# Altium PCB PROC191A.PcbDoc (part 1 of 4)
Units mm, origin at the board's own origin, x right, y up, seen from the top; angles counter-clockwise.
Board outline 150 x 100 mm, 6 copper layers (L1, L2, L3, L4, L5, L6), stack 1.608 mm thick; 309 components, 191 nets, 851 pads, 778 vias.
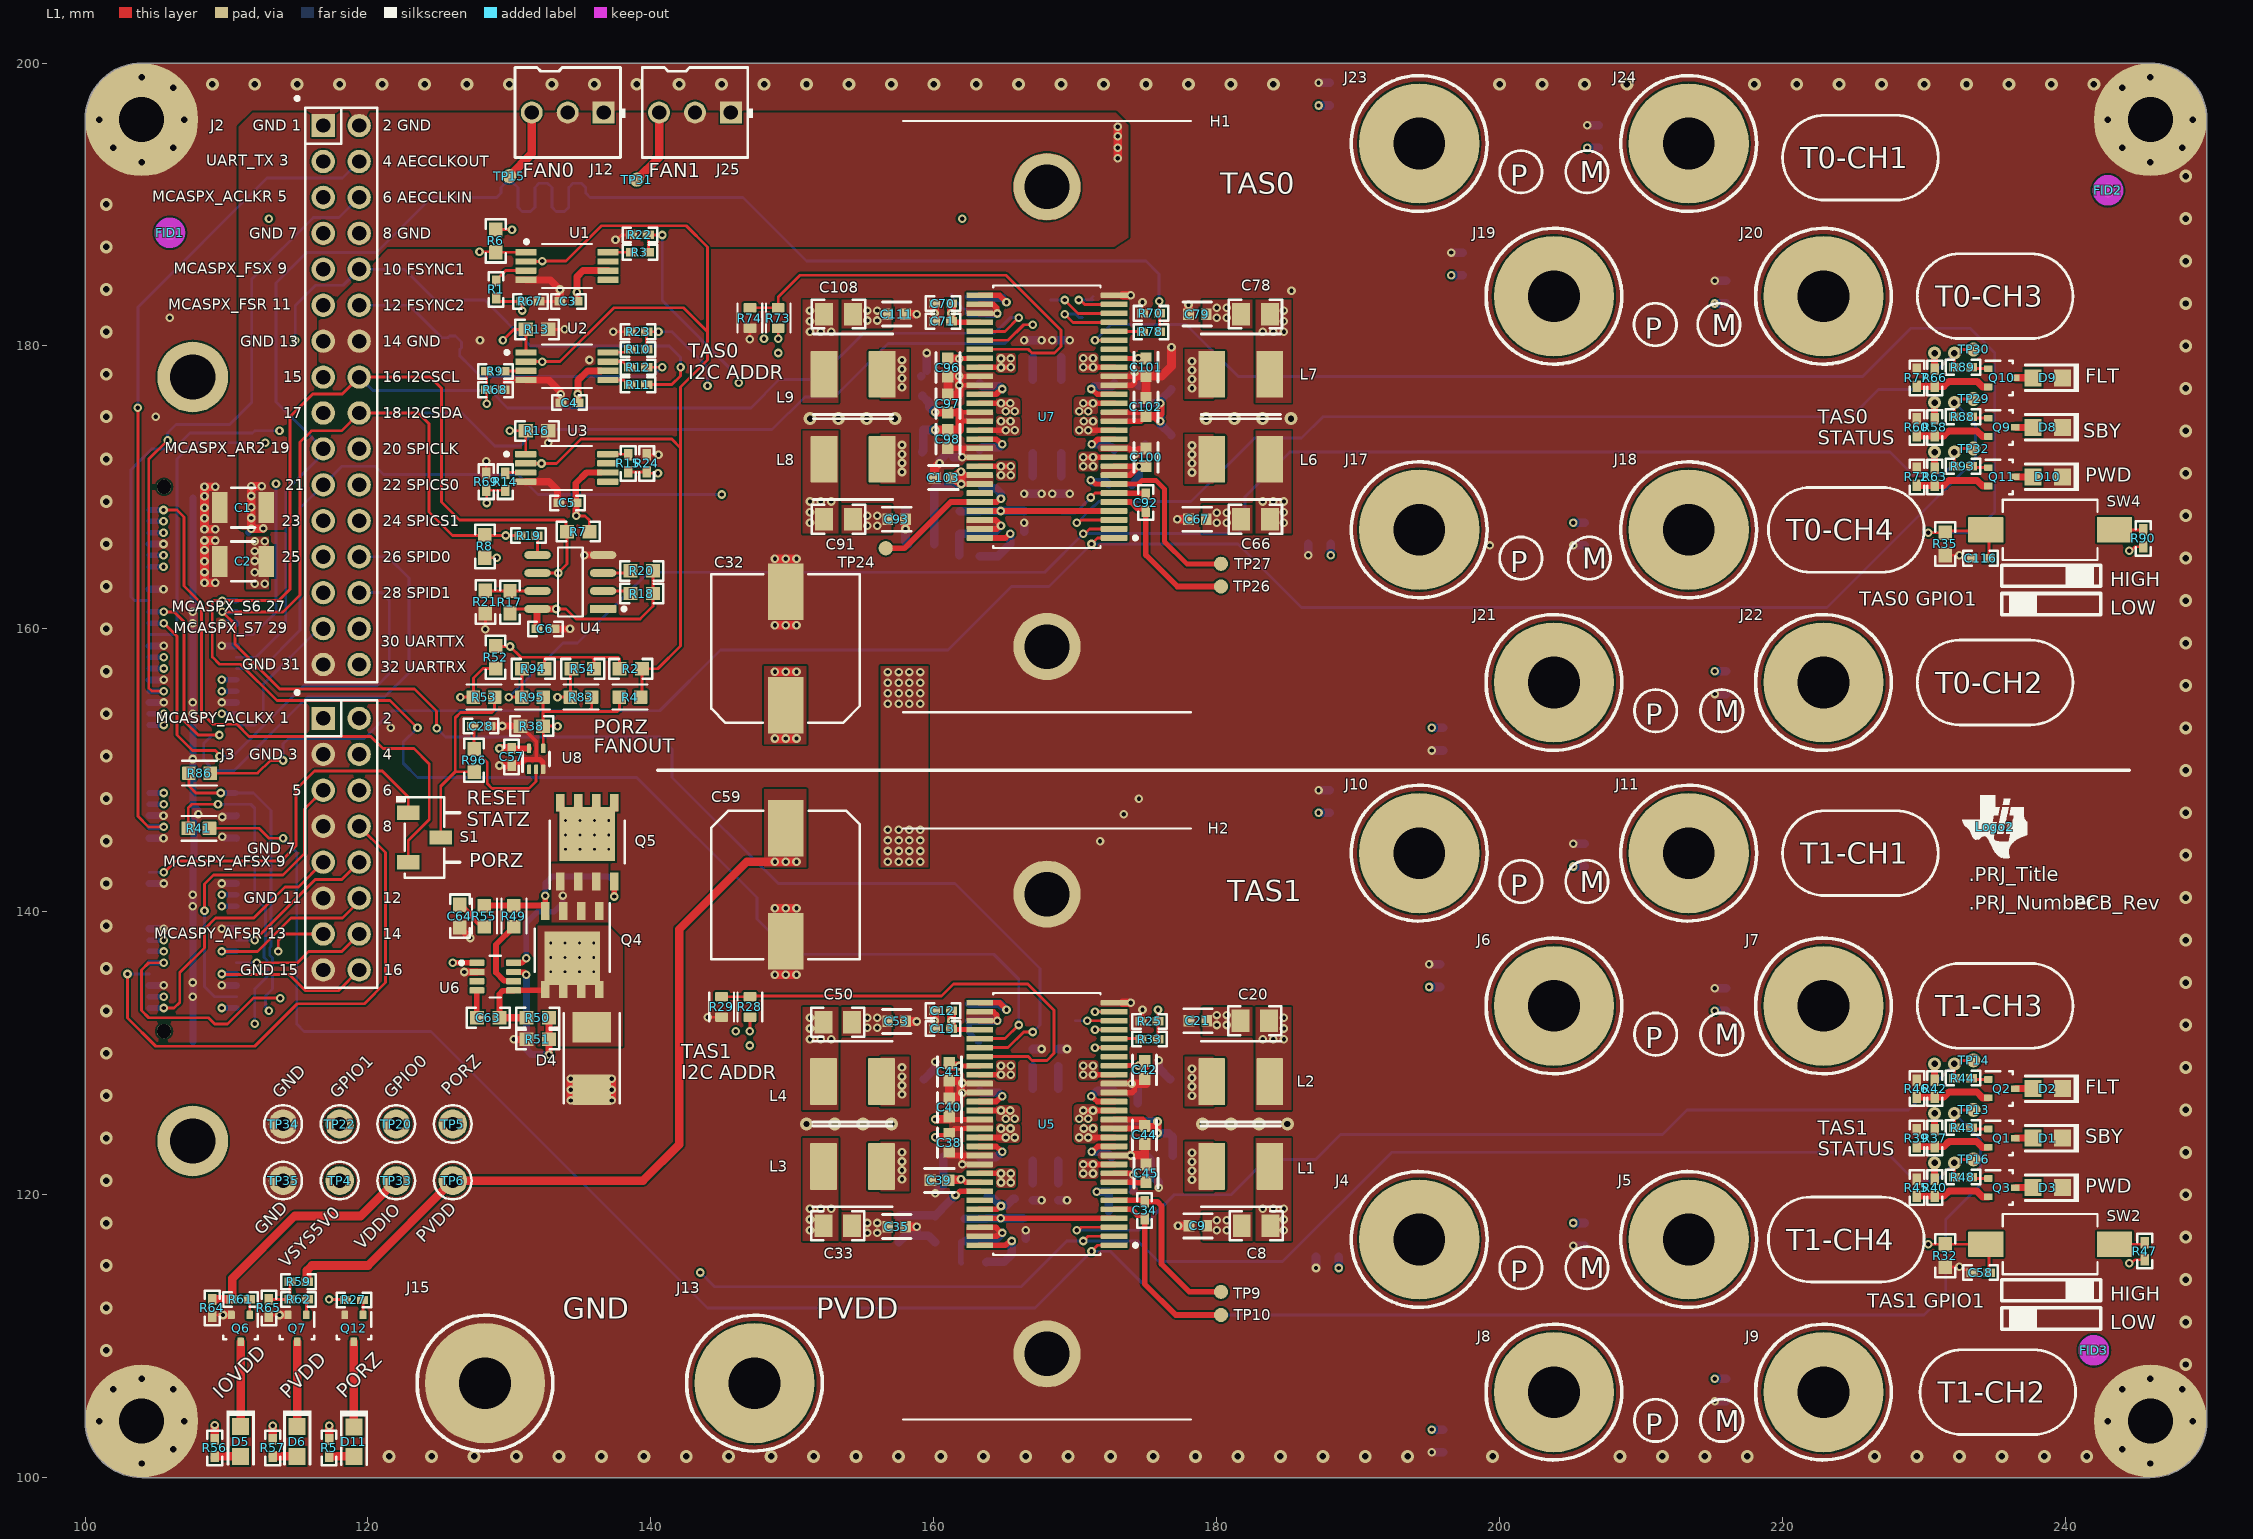
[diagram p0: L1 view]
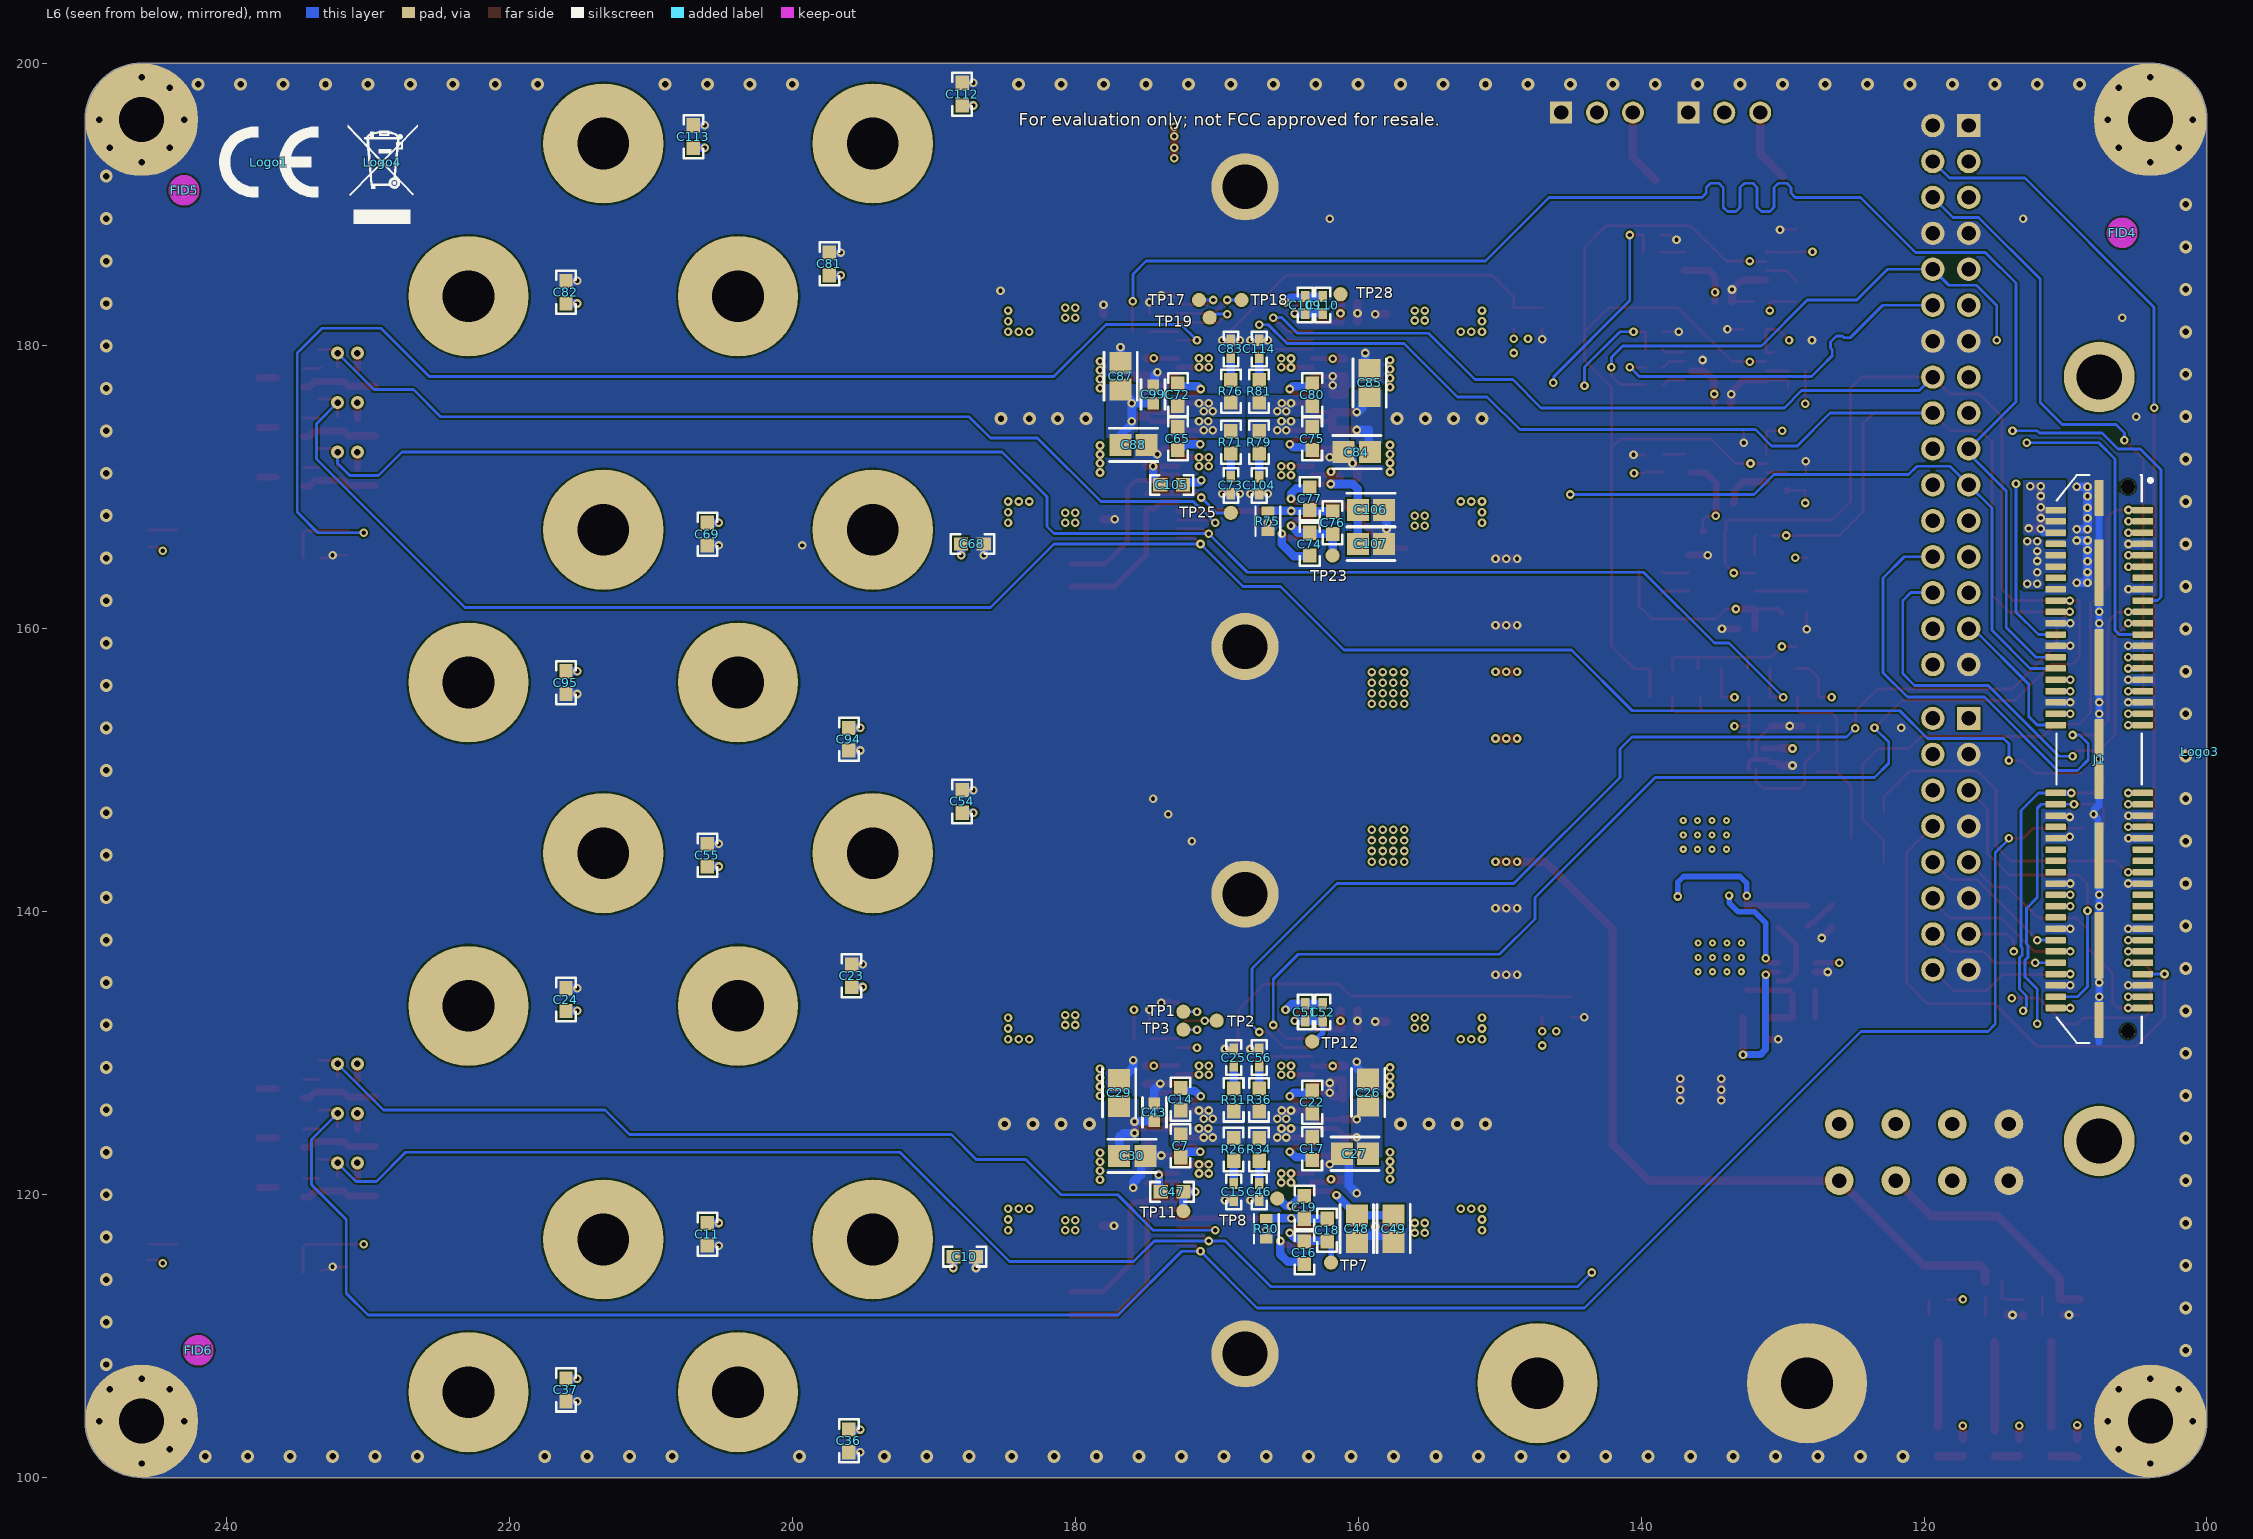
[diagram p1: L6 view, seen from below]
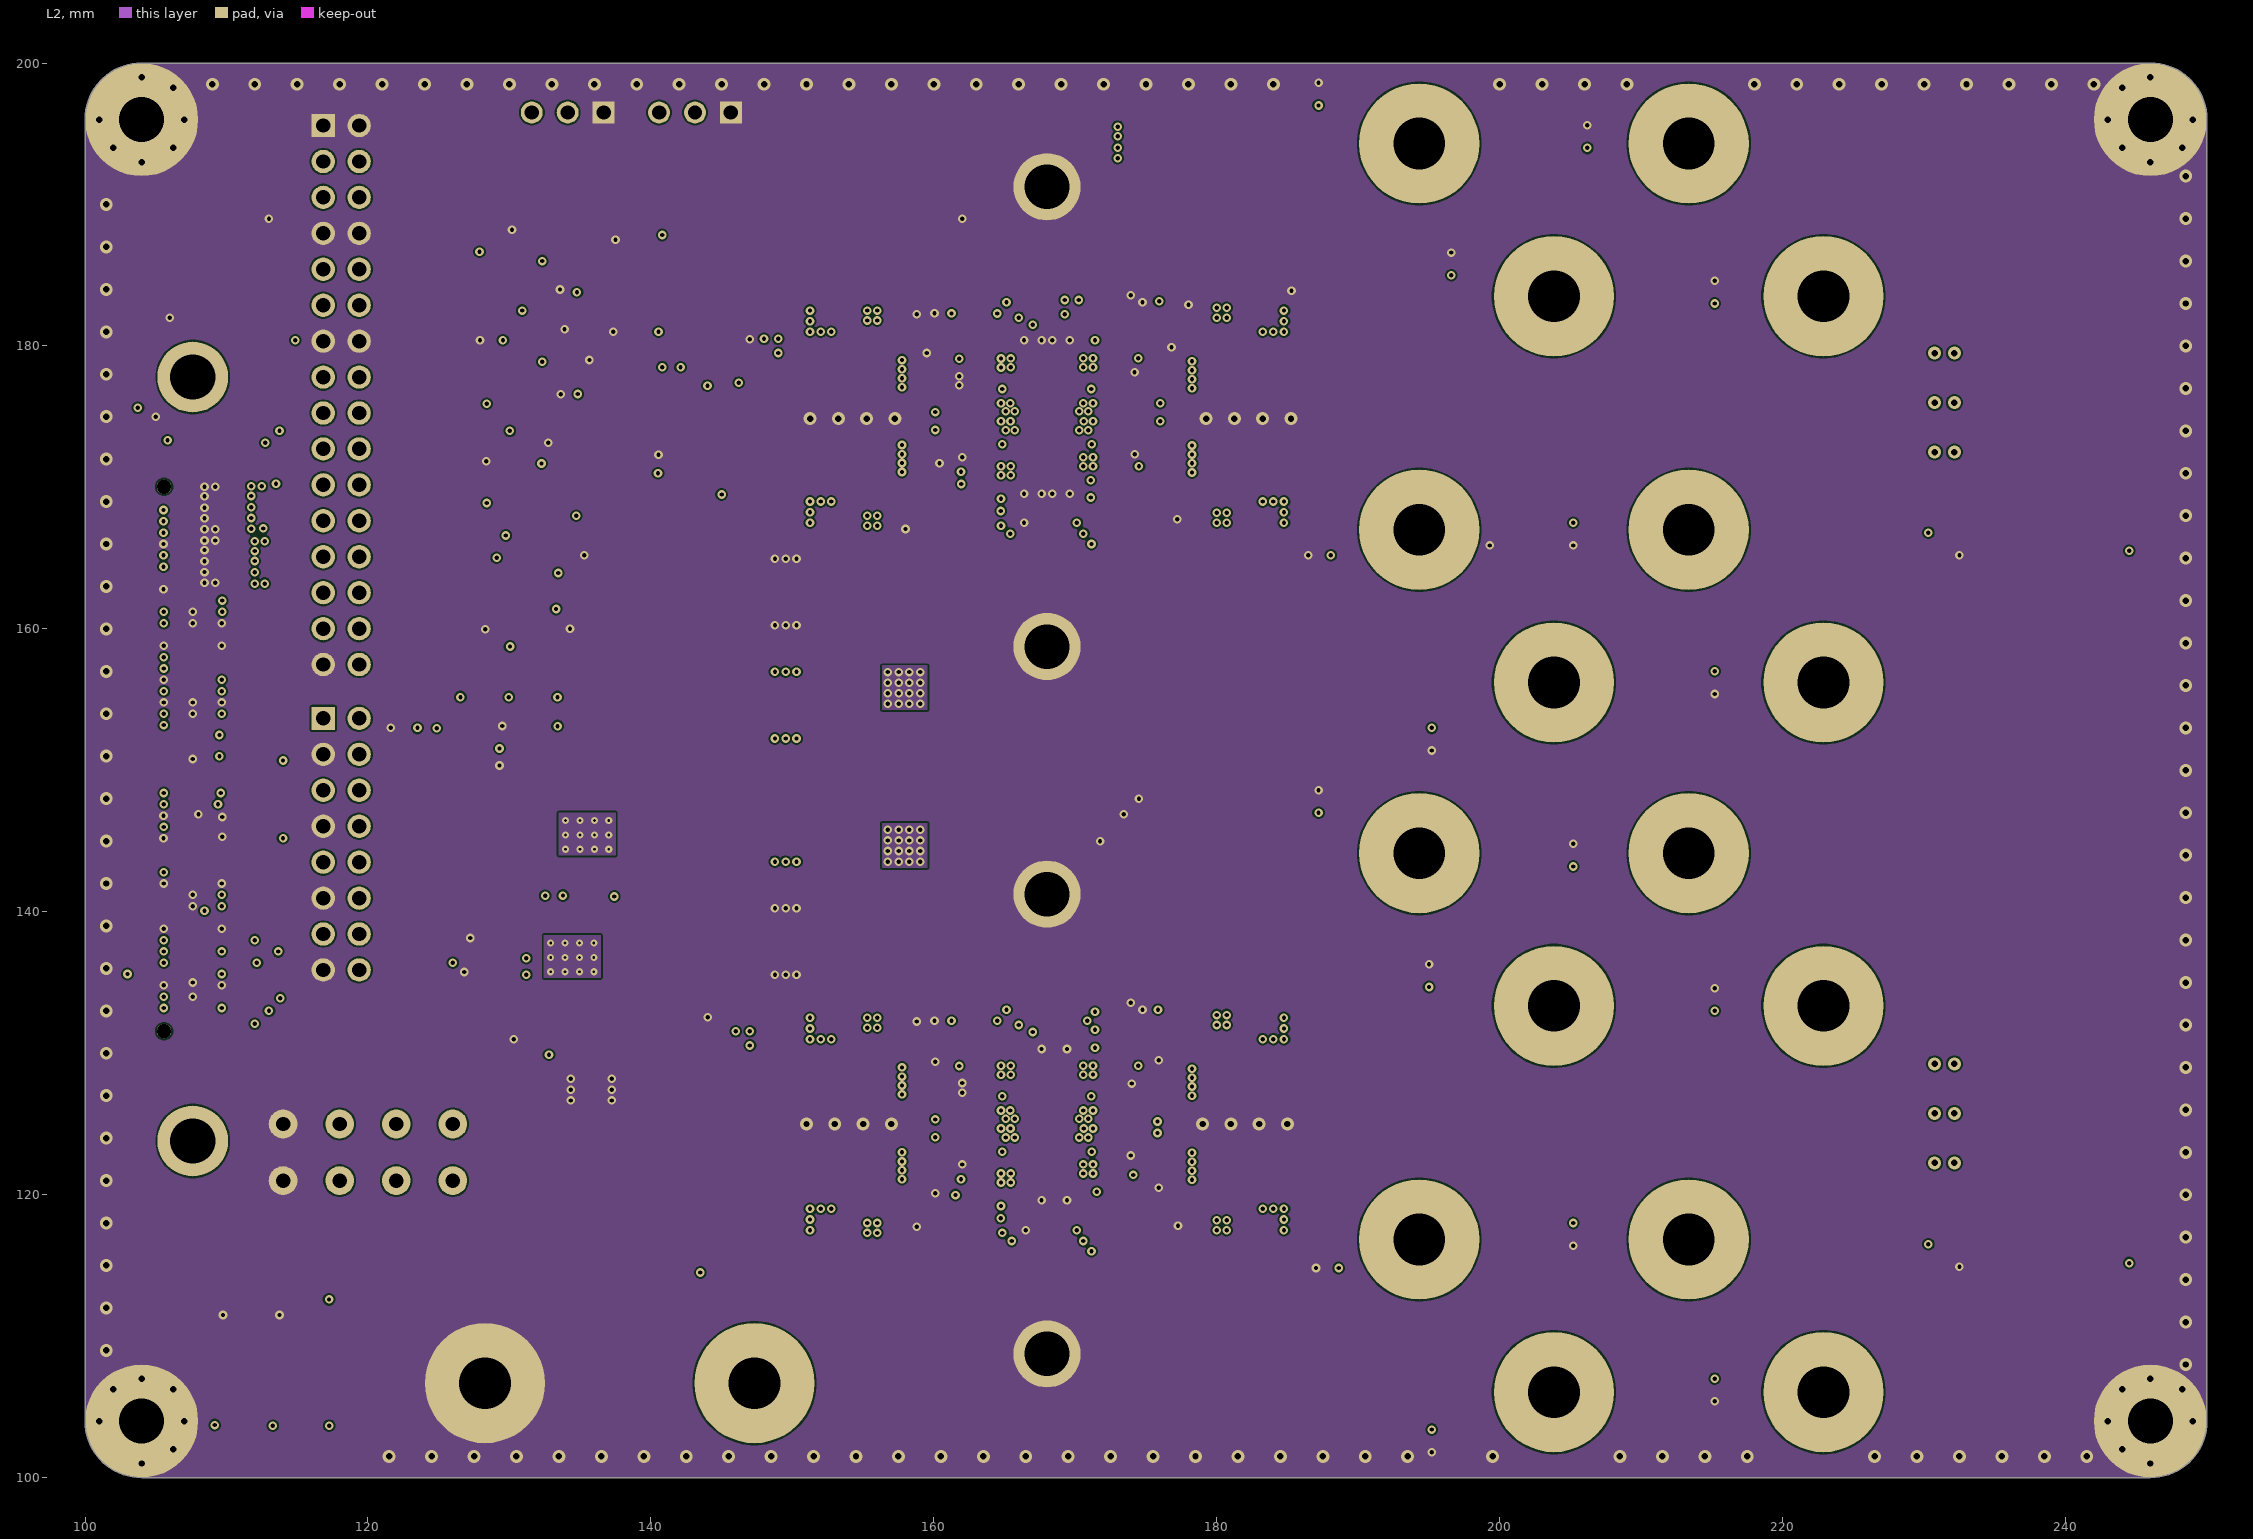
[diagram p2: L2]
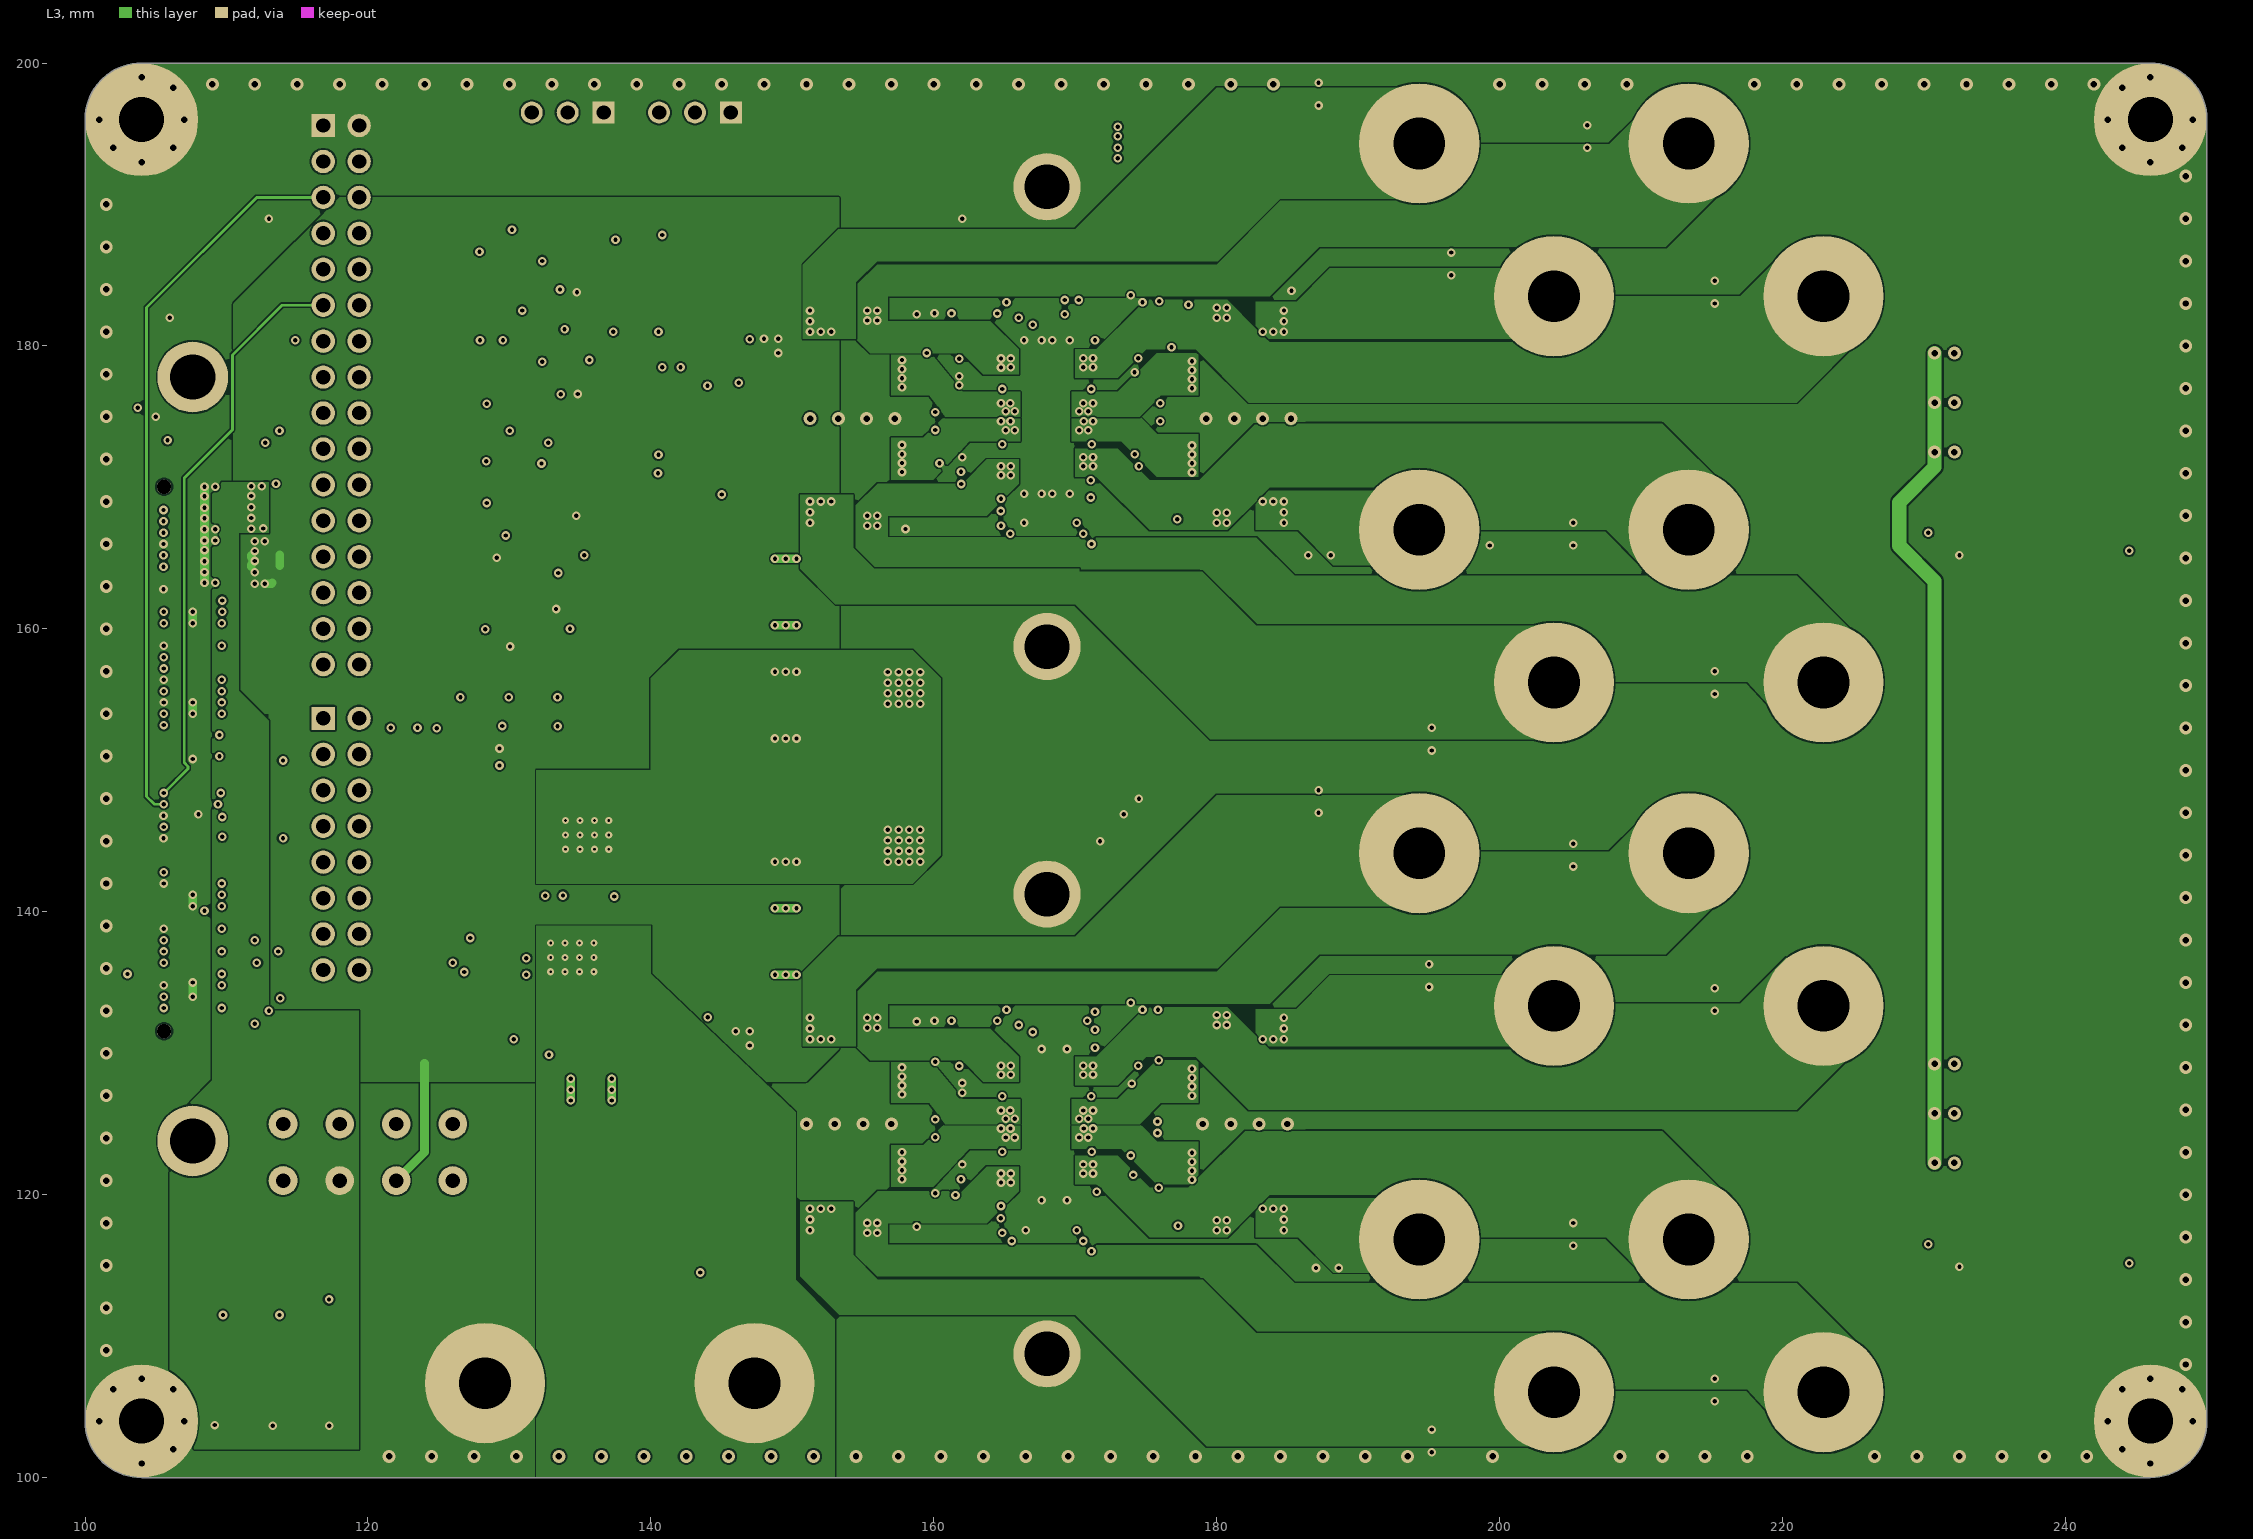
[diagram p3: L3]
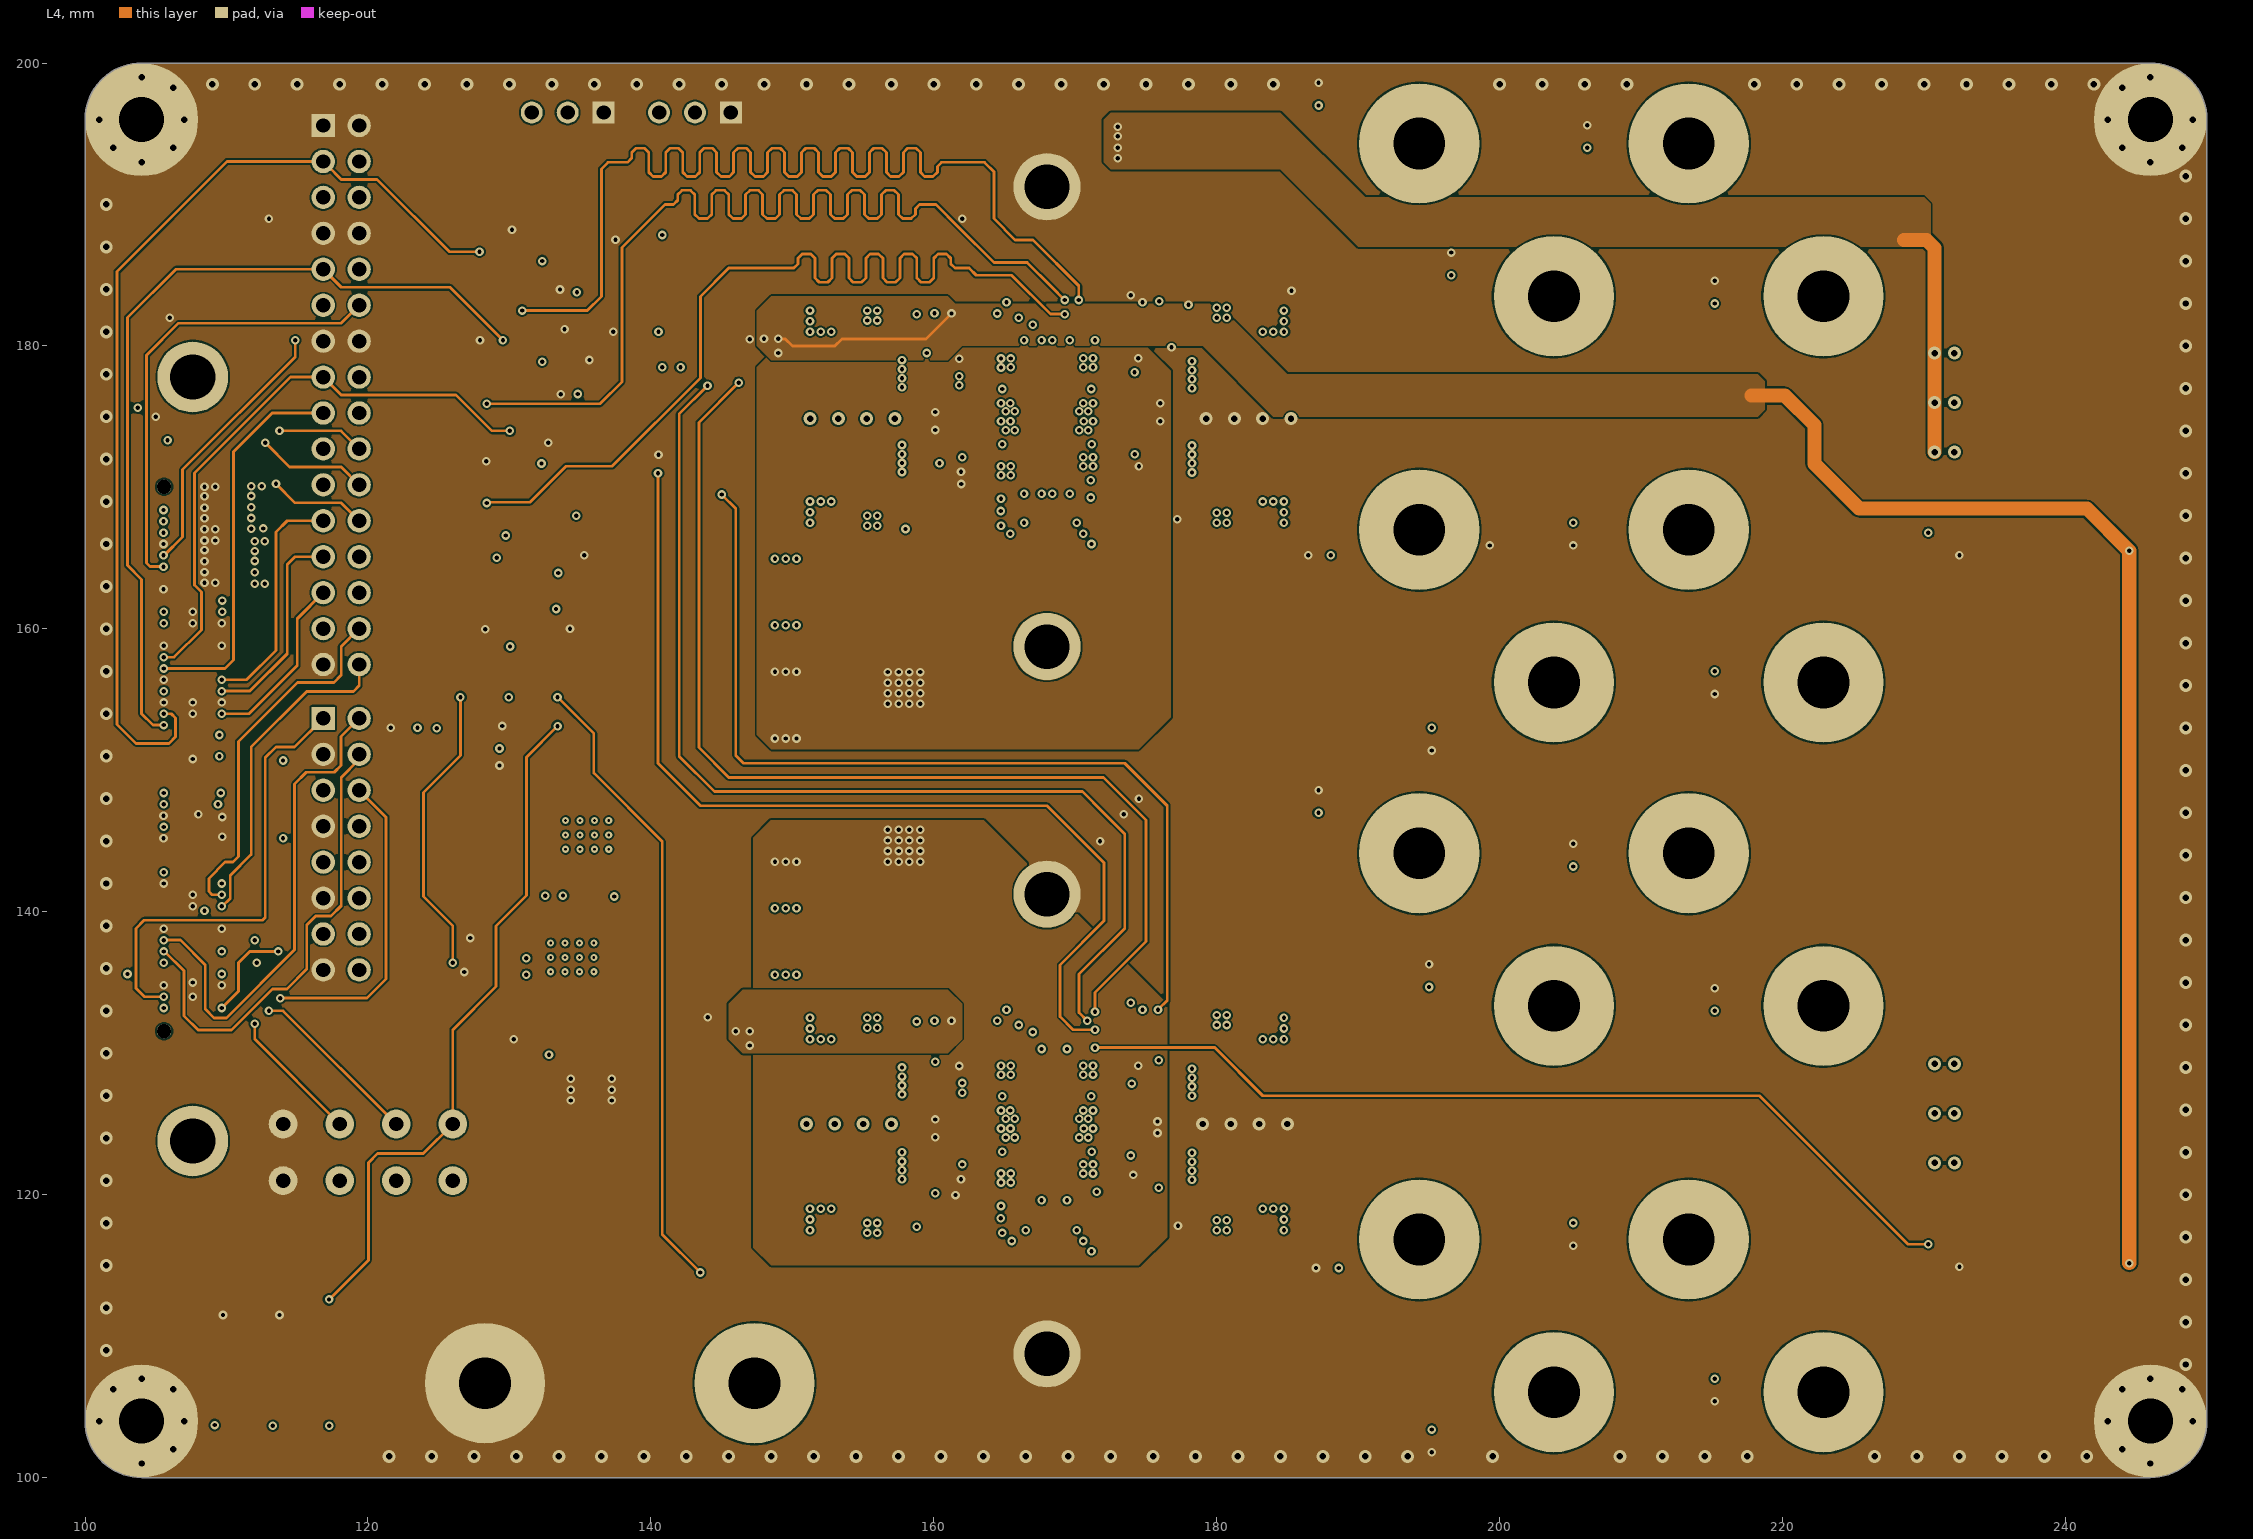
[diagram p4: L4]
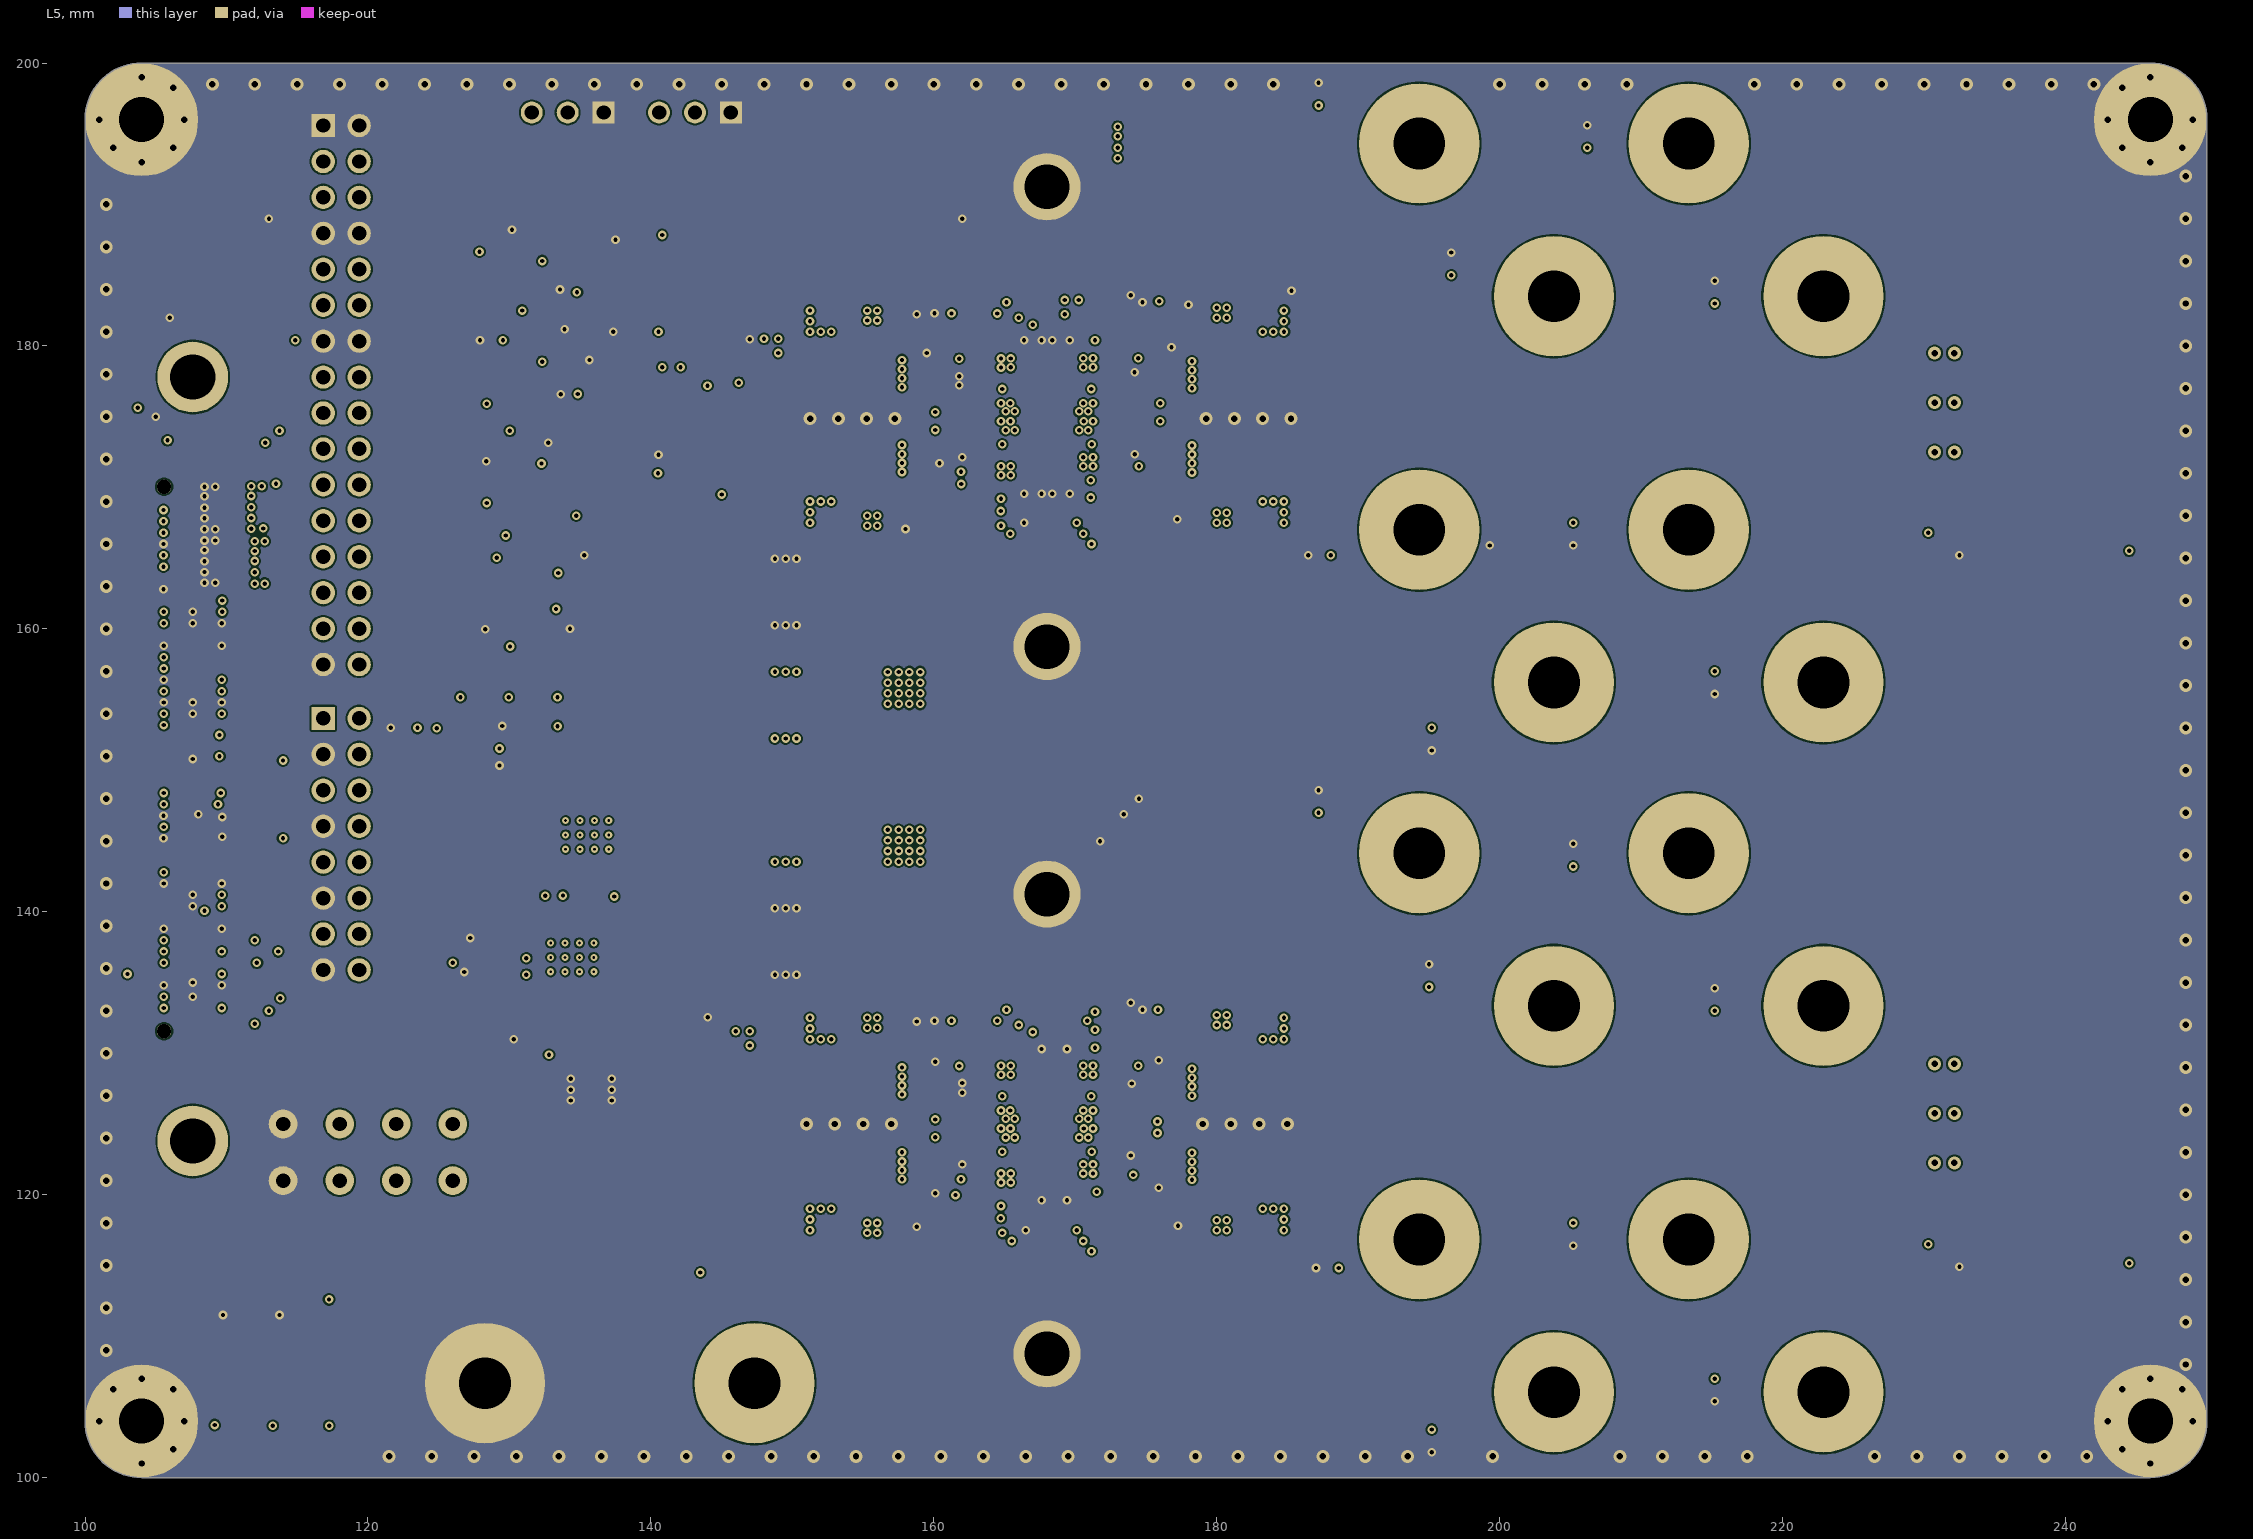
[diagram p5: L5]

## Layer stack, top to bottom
Top Solder: solder mask 0.0102, Solder Resist, Dk 3.5
L1: signal copper 0.018
Dielectric 1: core 0.1, Isola 370HR Core, Dk 4.17
L2: signal copper 0.018
Dielectric 3: prepreg 0.15, Isola 370HR Prepreg, Dk 4.17
L3: signal copper 0.018
Dielectric1: core 1, Isola 370HR Core, Dk 4.17
L4: signal copper 0.018
Dielectric 4: prepreg 0.15, Isola 370HR Prepreg, Dk 4.17
L5: signal copper 0.018
Dielectric 2: core 0.1, Isola 370HR Core, Dk 4.17
L6: signal copper 0.018
Bottom Solder: solder mask 0.0102, Solder Resist, Dk 3.5

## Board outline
104,100 cw(c104,104) 100,104 100,196 cw(c104,196) 104,200 246,200 cw(c246,196) 250,196 250,104 cw(c246,104) 246,100

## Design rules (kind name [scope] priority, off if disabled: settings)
AcuteAngle [All] p1: minimum=4.50000000000000E+0001 checktracksonly=FALSE
AssemblyTestPointUsage [All] p1: valid=2
BoardOutlineClearance BoardOutlineClearance_MountingHoles [OnCopper and InComponentClass('Mounting Holes')] p1: gap=1 ignorepadtopadclearanceinfootprint=FALSE
BoardOutlineClearance BoardOutlineClearance_Poly [OnCopper and IsPoly] p2: gap=0 ignorepadtopadclearanceinfootprint=FALSE
BoardOutlineClearance [OnCopper and Not InComponentClass('Logo') and not InComponentClass('FiducialMark') and not InRegion(1000,500,4000,800) and not InPoly] p3: gap=0.5 ignorepadtopadclearanceinfootprint=FALSE
Clearance Clearance_Keepouts [((IsTrack Or IsArc) And Not InPoly) And IsFree and IsKeepOut vs ((IsTrack Or IsArc) And Not InPoly) And IsFree and IsKeepOut] p1: gap=0 ignorepadtopadclearanceinfootprint=FALSE
Clearance Clearance_Poly [InPolygon] p2: gap=0.127 ignorepadtopadclearanceinfootprint=TRUE
Clearance Clearance_FiducialMark [IsKeepOut and InComponentClass('FiducialMark') vs IsPad and InComponentClass('FiducialMark')] p3: gap=0 ignorepadtopadclearanceinfootprint=TRUE
Clearance Clearance_1 [(ExistsOnLayer('L2') Or ExistsOnLayer('L3') Or ExistsOnLayer('L4') Or ExistsOnLayer('L5')) vs (ExistsOnLayer('L2') Or ExistsOnLayer('L3') Or ExistsOnLayer('L4') Or ExistsOnLayer('L5'))] p4: gap=0.127 ignorepadtopadclearanceinfootprint=TRUE sourcerule=58 cellrowname=All cellrowtype=0 cellcolname=All cellcoltype=0 innerlayers=TRUE
Clearance Clearance_2 [(ExistsOnLayer('L1') Or ExistsOnLayer('L6')) vs (ExistsOnLayer('L1') Or ExistsOnLayer('L6'))] p5: gap=0.127 ignorepadtopadclearanceinfootprint=TRUE sourcerule=58 cellrowname=All cellrowtype=0 cellcolname=All cellcoltype=0 outerlayers=TRUE
Clearance [All] p6: gap=0.2 ignorepadtopadclearanceinfootprint=TRUE ismatrix=TRUE
ComponentClearance ComponentClearance_Heatsink [HasFootprint('DKQ0056C-MFG') vs HasFootprint('FP-ATS-TI1OP-1918-C1-R0_HTSNK_41MM4_20MM0-MFG')] p1: gap=0 collisioncheckmode=3 verticalgap=0 showdistances=FALSE
ComponentClearance ComponentClearance_MountingHoles_FiducialMarks [InComponentClass('Mounting Holes') vs InComponentClass('FiducialMark')] p2: gap=1.27 collisioncheckmode=3 verticalgap=0.254 showdistances=FALSE
ComponentClearance ComponentClearance_Shunt [InComponentClass('Header') vs InComponentClass('Shunt')] p3: gap=0 collisioncheckmode=3 verticalgap=0 showdistances=FALSE
ComponentClearance ComponentClearance_Logo [InComponentClass('Logo')] p4: gap=0.762 collisioncheckmode=3 verticalgap=0.254 showdistances=FALSE
ComponentClearance ComponentClearance_ScrewToNut [(HasFootprint('NY PMS 440 0025 PH')) vs (HasFootprint('Keystone_1902C'))] p5: gap=0.127 collisioncheckmode=3 verticalgap=0.254 showdistances=FALSE
ComponentClearance ComponentClearance_MountingHoles [InComponentClass('Mounting Holes')] p6: gap=2.54 collisioncheckmode=3 verticalgap=2540 showdistances=FALSE
ComponentClearance ComponentClearance_SmallPassives [HasFootprint('0201*') or HasFootprint('0402*') or HasFootprint('0508') or HasFootprint('0603*') or HasFootprint('0612') or HasFootprint('0805*') or HasFootprint('0815*') or HasFootprint('0830*') or HasFootprint('1206*') or HasFootprint('1210*') or HasFootprint('1808*') or HasFootprint('1812*') or HasFootprint('1825*') or HasFootprint('2010*') or HasFootprint('2220*') or HasFootprint('2225*') or HasFootprint('2512*') or HasFootprint('2728*') or HasFootprint('3518*') vs HasFootprint('0201*') or HasFootprint('0402*') or HasFootprint('0508') or HasFootprint('0603*') or HasFootprint('0612') or HasFootprint('0805*') or HasFootprint('0815*') or HasFootprint('0830*') or HasFootprint('1206*') or HasFootprint('1210*') or HasFootprint('1808*') or HasFootprint('1812*') or HasFootprint('1825*') or HasFootprint('2010*') or HasFootprint('2220*') or HasFootprint('2225*') or HasFootprint('2512*') or HasFootprint('2728*') or HasFootprint('3518*')] p7: gap=0.38 collisioncheckmode=3 verticalgap=0.254 showdistances=FALSE
ComponentClearance ComponentClearance_THtoSMT [IsThruComponent vs IsSMTComponent] p8: gap=0.762 collisioncheckmode=3 verticalgap=0.762 showdistances=FALSE
ComponentClearance ComponentClearance_THtoTH [IsThruComponent vs IsThruComponent] p9: gap=0.508 collisioncheckmode=3 verticalgap=0.762 showdistances=FALSE
ComponentClearance [All] p10: gap=0.025 collisioncheckmode=3 verticalgap=0.025 showdistances=FALSE
FabricationTestPointUsage TestPointUsage [All] p1: valid=2 allowmultiple=FALSE
FabricationTestpoint Testpoint [All] p1: side=3 testpointundercomponent=TRUE minsize=1.016 maxsize=2.54 preferedsize=1.524 minholesize=0 maxholesize=1.016 preferedholesize=0.813 testpointgrid=0.025 allowsidetop=TRUE allowsidebottom=TRUE usegrid=TRUE gridtolerance=0
FanoutControl Fanout_LCC [IsLCC] p1: bgadir=Out bgaviamode=Centered fanoutstyle=Auto fanoutdirection=Alternating viagrid=0.025 // Fanout_LCC (Default Rule)
FanoutControl Fanout_BGA [IsBGA] p2: bgadir=Out bgaviamode=Centered fanoutstyle=Auto fanoutdirection=Alternating viagrid=0.025 // Fanout_BGA (Default Rule)
FanoutControl Fanout_Default [All] p4: bgadir=Out bgaviamode=Centered fanoutstyle=Auto fanoutdirection=Alternating viagrid=0.025 // Fanout_Default (Default Rule)
FanoutControl Fanout_Small [(CompPinCount < 5)] p5: bgadir=Out bgaviamode=Centered fanoutstyle=Auto fanoutdirection=OutThenIn viagrid=0.025 // Fanout_Small (Default Rule)
Height [All] p1: minheight=0 maxheight=50 prefheight=12.7
HoleSize [All] p1: absolutevalues=TRUE maxlimit=6.375 minlimit=0.2 maxpercent=80.000 minpercent=20.000
MinimumAnnularRing MinimumAnnularRing_ThermalPadVias [IsVia and InAnyComponent] p1: minimumring=0.051
MinimumAnnularRing [All] p2: minimumring=0.051
MinimumSolderMaskSliver MinimumSolderMaskSliver_Logo [InComponentClass('Logo') vs InComponentClass('Logo')] p1: minsoldermaskwidth=0.018
MinimumSolderMaskSliver [All] p2: minsoldermaskwidth=0.1
PlaneConnect [All] p1: planeconnectstyle=Direct reliefexpansion=0.254 reliefentries=4 reliefconductorwidth=0.254 reliefairgap=0.254
PolygonConnect [All] p1: connectstyle=Direct reliefconductorwidth=0.254 reliefentries=4 polygonreliefangle="90 Angle" airgapwidth=0.254
RoutingVias [All] p1: holewidth=0.711 width=1.27 viastyle="Through Hole" minholewidth=0.711 minwidth=1.27 maxholewidth=0.711 maxwidth=1.27
SilkToBoardRegionClearance [Not ((IsComment or IsDesignator) And (Hide <> 'False')) and not InRegion(1000,500,4000,800)] p1:
SilkToSilkClearance SilkToSilkClearance_Pb-FreeLogo [(HasFootprint('Pb-Free_Overlay_Medium') OR HasFootprint('Pb-Free_Overlay_Small')) vs (HasFootprint('Pb-Free_Overlay_Medium') OR HasFootprint('Pb-Free_Overlay_Small'))] p1: silktosilkclearance=0
SilkToSilkClearance [All] p2: silktosilkclearance=0.1
SilkToSolderMaskClearance SilkToComponentPadClearance [(IsPad or IsFill or IsRegion) and InAnycomponent] p1: minsilkscreentomaskgap=0.051 clearancetoexposedcopper=TRUE
SilkToSolderMaskClearance "Silk to Solder Mask Opening" [All] p2: minsilkscreentomaskgap=0.051 clearancetoexposedcopper=FALSE
SolderMaskExpansion [All] p1: expansion=0.05 istentingtop=FALSE
UnRoutedNet [All] p1: checkbadconnections=TRUE
Width MaxMinWidth_2 [All] p1: maxlimit=25 minlimit=0.1 preferedwidth=0.4 minimp=50.000000 maximp=50.000000 favimp=50.000000
Width MaxMinWidth_1 [All] p2: maxlimit=0.254 minlimit=0.254 preferedwidth=0.254
14 further rules are at their usual default settings.

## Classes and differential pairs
net class POWER: AREF0 AREF1 AVSS0 AVSS1 CP0 CP1 CPC_BOT0 CPC_BOT1 CPC_TOP0 CPC_TOP1 GVDD0 GVDD1 PLL_BYP0 PLL_BYP1 PVDD PVDD_CONN VR_RET0 VR_RET1 VREG0 VREG1
net class AUDIO_OUTPUT: BST_1P0 BST_1P1 BST_2P0 BST_2P1 BST_3P BST_3P0 BST_4P0 BST_4P1 OUT_1M_J0 OUT_1M_J1 OUT_1P0 OUT_1P1 OUT_2M_J0 OUT_2M_J1 OUT_2P0 OUT_2P1 OUT_3M_J0 OUT_3M_J1 OUT_3P0 OUT_3P1 OUT_4M_J0 OUT_4M_J1 OUT_4P0 OUT_4P1
net class SPI: SPI_CLK SPI_CS0 SPI_CS1 SPI_D0 SPI_D1
net class I2C0: I2C_SCL I2C_SDA I2C_SDA_R
net class MCASPY: McASPy_ACLKR McASPy_ACLKX MCASPY_AFSR McASPy_AFSX McASPy_Serial0 McASPy_Serial1 McASPy_Serial2 McASPy_Serial3 McASPy_Serial4 McASPy_Serial5 McASPy_Serial6 McASPy_Serial7
net class MCASPX: MCASPX_ACLKR MCASPX_ACLKX MCASPX_ACLKX0 MCASPX_ACLKX0_R MCASPX_ACLKX1 MCASPX_ACLKX1_R MCASPX_AR2 MCASPX_AR3 MCASPX_AX0 MCASPX_AX00 MCASPX_AX00_R MCASPX_AX1 MCASPX_AX01 MCASPX_AX01_R MCASPX_FSR MCASPX_FSX MCASPX_FSX0 MCASPX_FSX0_R MCASPX_FSX1 MCASPX_FSX1_R MCASPX_FSX2_R MCASPX_FSX3_R MCASPX_SERIAL4 MCASPX_SERIAL5 MCASPX_SERIAL6 MCASPX_SERIAL7
component class PROC191_Hardware: !PCB1 FID1 FID2 FID3 FID4 FID5 FID6 Logo1 Logo2 Logo3 Logo4 ZZ2 ZZ3 ZZ4
component class Logo: Logo2
component class FiducialMark: FID1 FID2 FID3 FID4 FID5 FID6
component class AssemblyNote: ZZ2 ZZ3 ZZ4
component class PROC191_TAS1: C7 C8 C9 C10 C11 C12 C13 C14 C15 C16 C17 C18 C19 C20 C21 C22 C23 C24 C25 C26 C27 C29 C30 C32 C33 C34 C35 C36 C37 C38 C39 C40 C41 C42 C43 C44 C45 C46 C47 C48 C49 C50 C51 C52 C53 C54 C55 C56 C58 D1 D2 D3 H1 J4 J5 J6 J7 J8 J9 J10 J11 J12 L1 L2 L3 L4 Q1 Q2 Q3 R22 R23 R24 R25 R26 R28 R29 R30 R31 R32 R33 R34 R36 R37 R41 R42 R43 R44 R45 R47 R48 R54 R83 SW2 TP1 TP2 TP3 TP7 TP8 TP9 TP10 TP11 TP12 TP13 TP14 TP15 TP16 U5
component class PROC191_TAS0: C59 C65 C66 C67 C68 C69 C70 C71 C72 C73 C74 C75 C76 C77 C78 C79 C80 C81 C82 C83 C84 C85 C87 C88 C91 C92 C93 C94 C95 C96 C97 C98 C99 C100 C101 C102 C103 C104 C105 C106 C107 C108 C109 C110 C111 C112 C113 C114 C116 D8 D9 D10 H2 J17 J18 J19 J20 J21 J22 J23 J24 J25 L6 L7 L8 L9 Q9 Q10 Q11 R35 R58 R60 R63 R66 R67 R68 R69 R70 R71 R72 R73 R74 R75 R76 R77 R78 R79 R81 R86 R88 R89 R90 R93 R94 R95 SW4 TP17 TP18 TP19 TP23 TP24 TP25 TP26 TP27 TP28 TP29 TP30 TP31 TP32 U7
component class PROC191_Power: C63 C64 D4 D5 D6 D11 J13 J15 Q4 Q5 Q6 Q7 Q12 R5 R27 R49 R50 R51 R52 R53 R55 R56 R57 R59 R61 R62 R64 R65 U6
component class Header: J2 J3 J12 J25
component class PROC191_ExpansionConnector: C1 C2 C3 C4 C5 C6 C28 C57 J1 J2 J3 R1 R2 R3 R4 R6 R7 R8 R9 R10 R11 R12 R13 R14 R15 R16 R17 R18 R19 R20 R21 R38 R96 S1 TP4 TP5 TP6 TP20 TP22 TP33 TP34 TP35 U1 U2 U3 U4 U8

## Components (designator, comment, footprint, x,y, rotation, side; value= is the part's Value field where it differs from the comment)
C1 "C1210C475K5RACAUTO" 1210_280 111.176,168.572 r0 top value=4.7uF
C2 "C1210C475K5RACAUTO" 1210_280 111.176,164.77 r0 top value=4.7uF
C3 "GRM155R71E104KE14D" 0402 134.173,183.148 r0 top value=0.1uF
C4 "GRM155R71E104KE14D" 0402 134.25,176 r0 top value=0.1uF
C5 "GRM155R71E104KE14D" 0402 134.1,168.9 r0 top value=0.1uF
C6 "GRM155R71E104KE14D" 0402 132.55,160 r180 top value=0.1uF
C7 "GCM188R71C105KA64D" 0603 172.553,123.45 r90 bottom value=1uF
C8 "GCM21BR71H105KA03K" 0805_HV 182.784,117.8 r180 top value=1uF
C9 "GCM188R71H154KA64D" FP-GCM188-0_1-IPC_C 178.673,117.8 r180 top
C10 "GRM1885C1H103JA01D" 0603 187.817,115.618 r180 bottom value=0.01uF
C11 "GRM1885C1H103JA01D" 0603 206,117.2 r270 bottom value=0.01uF
C12 "GRM155R70J105KA12D" 0402 160.65,133 r180 top value=1uF
C13 "GRM155R70J104KA01D" 0402 160.65,131.75 r180 top value=0.1uF
C14 "GCM188R71C105KA64D" 0603 172.553,126.752 r270 bottom value=1uF
C15 "GRM155R71H331KA01D" 0402 168.8,120.2 r90 bottom value=330pF
C16 "GCM188R71C105MA64D" 0603 163.8,115.9 r90 bottom value=1uF
C17 "GCM188R71C105KA64D" 0603 163.25,123.262 r90 bottom value=1uF
C18 "GCM188R71C105MA64D" 0603 162.2,117.5 r90 bottom value=1uF
C19 "EMK107BB7225KA-T" 0603 163.8,119.1 r90 bottom value=2.2uF
C20 "GCM21BR71H105KA03K" 0805_HV 182.684,132.3 r180 top value=1uF
C21 "GCM188R71H154KA64D" FP-GCM188-0_1-IPC_C 178.673,132.3 r180 top
C22 "GCM188R71C105KA64D" 0603 163.25,126.55 r270 bottom value=1uF
C23 "GRM1885C1H103JA01D" 0603 195.81,135.486 r90 bottom value=0.01uF
C24 "GRM1885C1H103JA01D" 0603 216,133.8 r90 bottom value=0.01uF
C25 "GRM155R71H331KA01D" 0402 168.8,129.7 r270 bottom value=330pF
C26 "GCJ21BR71H105MA01L" FP-GCJ21B-0_3-IPC_A 159.3,127.225 r90 bottom
C27 "GCJ21BR71H105MA01L" FP-GCJ21B-0_3-IPC_A 160.227,122.897 r0 bottom
C28 "GRM155R71E103KA01D" 0402 128,153.134 r0 top value=0.01uF
C29 "GCJ21BR71H105MA01L" FP-GCJ21B-0_3-IPC_A 176.9,127.2 r90 bottom
C30 "GCJ21BR71H105MA01L" FP-GCJ21B-0_3-IPC_A 175.975,122.749 r180 bottom
C32 "UCL1V391MNL1GS" SM_RADIAL_10BMM 149.53,158.61 r90 top locked value=390uF
C33 "GCM21BR71H105KA03K" 0805_HV 153.216,117.8 r0 top value=1uF
C34 "GCM155R71C104KA55D" 0402 174.9,118.9 r90 top value=0.1uF
C35 "GCM188R71H154KA64D" FP-GCM188-0_1-IPC_C 157.377,117.75 r0 top
C36 "GRM1885C1H103JA01D" 0603 196,102.6 r270 bottom value=0.01uF
C37 "GRM1885C1H103JA01D" 0603 216,106.2 r270 bottom value=0.01uF
C38 "GCJ188R71H104KA12D" FP-GCJ188-0_2-IPC_C 161.1,123.675 r90 top
C39 "GCJ188R71H104KA12D" FP-GCJ188-0_2-IPC_C 160.398,121.014 r0 top
C40 "GCJ188R71H104KA12D" FP-GCJ188-0_2-IPC_C 161.1,126.175 r270 top
C41 "GCJ188R71H104KA12D" FP-GCJ188-0_2-IPC_C 161.1,128.7 r90 top
C42 "GCJ188R71H104KA12D" FP-GCJ188-0_2-IPC_C 174.9,128.825 r90 top
C43 "GCJ188R71H104KA12D" FP-GCJ188-0_2-IPC_C 174.4,125.825 r270 bottom
C44 "GCJ188R71H104KA12D" FP-GCJ188-0_2-IPC_C 174.9,124.225 r90 top
C45 "GCJ188R71H104KA12D" FP-GCJ188-0_2-IPC_C 175,121.525 r270 top
C46 "GRM155R71H331KA01D" 0402 167,120.2 r90 bottom value=330pF
C47 "GRM188R71C334KA01D" 0603 173.161,120.209 r0 bottom value=0.33uF
C48 "GCJ21BR71H105MA01L" FP-GCJ21B-0_3-IPC_A 160.1,117.6 r270 bottom
C49 "GCJ21BR71H105MA01L" FP-GCJ21B-0_3-IPC_A 157.5,117.6 r270 bottom
C50 "GCM21BR71H105KA03K" 0805_HV 153.216,132.2 r0 top value=1uF
C51 "GRM155R70J105KA12D" 0402 163.734,132.903 r90 bottom value=1uF
C52 "GRM155R70J105KA12D" 0402 162.5,132.903 r90 bottom value=1uF
C53 "GCM188R71H154KA64D" FP-GCM188-0_1-IPC_C 157.377,132.25 r0 top
C54 "GRM1885C1H103JA01D" 0603 188,147.8 r90 bottom value=0.01uF
C55 "GRM1885C1H103JA01D" 0603 206,144 r90 bottom value=0.01uF
C56 "GRM155R71H331KA01D" 0402 167,129.7 r270 bottom value=330pF
C57 "GRM155R71E104KE14D" 0402 130.15,150.945 r90 top value=0.1uF
C58 "C0402C104K4RACAUTO" 0402 234,114.5 r180 top value=0.1uF
C59 "UCL1V391MNL1GS" SM_RADIAL_10BMM 149.53,141.91 r270 top locked value=390uF
C63 "GCM188R71H104KA57D" 0603 128.5,132.512 r180 top value=0.1uF
C64 "CGA3E3X5R1H105M080AB" 0603 126.5,139.7 r270 top value=1uF
C65 "GCM188R71C105KA64D" 0603 172.75,173.45 r90 bottom value=1uF
C66 "GCM21BR71H105KA03K" 0805_HV 182.734,167.75 r180 top value=1uF
C67 "GCM188R71H154KA64D" FP-GCM188-0_1-IPC_C 178.627,167.75 r180 top
C68 "GRM1885C1H103JA01D" 0603 187.267,166 r180 bottom value=0.01uF
C69 "GRM1885C1H103JA01D" 0603 206,166.7 r270 bottom value=0.01uF
C70 "GRM155R70J105KA12D" 0402 160.65,183 r180 top value=1uF
C71 "GRM155R70J104KA01D" 0402 160.65,181.75 r180 top value=0.1uF
C72 "GCM188R71C105KA64D" 0603 172.75,176.55 r270 bottom value=1uF
C73 "GRM155R71H331KA01D" 0402 169,170.15 r90 bottom value=330pF
C74 "GCM188R71C105MA64D" 0603 163.425,165.992 r90 bottom value=1uF
C75 "GCM188R71C105KA64D" 0603 163.25,173.45 r90 bottom value=1uF
C76 "GCM188R71C105MA64D" 0603 161.801,167.5 r90 bottom value=1uF
C77 "EMK107BB7225KA-T" 0603 163.425,169.205 r90 bottom value=2.2uF
C78 "GCM21BR71H105KA03K" 0805_HV 182.734,182.25 r180 top value=1uF
C79 "GCM188R71H154KA64D" FP-GCM188-0_1-IPC_C 178.623,182.25 r180 top
C80 "GCM188R71C105KA64D" 0603 163.25,176.55 r270 bottom value=1uF
C81 "GRM1885C1H103JA01D" 0603 197.383,185.8 r90 bottom value=0.01uF
C82 "GRM1885C1H103JA01D" 0603 216,183.8 r90 bottom value=0.01uF
C83 "GRM155R71H331KA01D" 0402 169,179.8 r270 bottom value=330pF
C84 "GCJ21BR71H105MA01L" FP-GCJ21B-0_3-IPC_A 160.1,172.5 r0 bottom
C85 "GCJ21BR71H105MA01L" FP-GCJ21B-0_3-IPC_A 159.2,177.387 r90 bottom
C87 "GCJ21BR71H105MA01L" FP-GCJ21B-0_3-IPC_A 176.8,177.858 r90 bottom
C88 "GCJ21BR71H105MA01L" FP-GCJ21B-0_3-IPC_A 175.875,173 r180 bottom
C91 "GCM21BR71H105KA03K" 0805_HV 153.266,167.75 r0 top value=1uF
C92 "GCM155R71C104KA55D" 0402 174.99,168.923 r90 top value=0.1uF
C93 "GCM188R71H154KA64D" FP-GCM188-0_1-IPC_C 157.377,167.75 r0 top
C94 "GRM1885C1H103JA01D" 0603 196,152.2 r270 bottom value=0.01uF
C95 "GRM1885C1H103JA01D" 0603 216,156.2 r270 bottom value=0.01uF
C96 "GCJ188R71H104KA12D" FP-GCJ188-0_2-IPC_C 161,178.475 r90 top
C97 "GCJ188R71H104KA12D" FP-GCJ188-0_2-IPC_C 161,175.925 r270 top
C98 "GCJ188R71H104KA12D" FP-GCJ188-0_2-IPC_C 161,173.413 r90 top
C99 "GCJ188R71H104KA12D" FP-GCJ188-0_2-IPC_C 174.5,176.578 r270 bottom
C100 "GCJ188R71H104KA12D" FP-GCJ188-0_2-IPC_C 175,172.125 r270 top
C101 "GCJ188R71H104KA12D" FP-GCJ188-0_2-IPC_C 175,178.5 r90 top
C102 "GCJ188R71H104KA12D" FP-GCJ188-0_2-IPC_C 175,175.693 r270 top
C103 "GCJ188R71H104KA12D" FP-GCJ188-0_2-IPC_C 160.675,170.7 r0 top
C104 "GRM155R71H331KA01D" 0402 167,170.15 r90 bottom value=330pF
C105 "GRM188R71C334KA01D" 0603 173.19,170.18 r0 bottom value=0.33uF
C106 "GCJ21BR71H105MA01L" FP-GCJ21B-0_3-IPC_A 159.1,168.405 r180 bottom
C107 "GCJ21BR71H105MA01L" FP-GCJ21B-0_3-IPC_A 159.1,166 r180 bottom
C108 "GCM21BR71H105KA03K" 0805_HV 153.266,182.25 r0 top value=1uF
C109 "GRM155R70J105KA12D" 0402 163.75,182.891 r90 bottom value=1uF
C110 "GRM155R70J105KA12D" 0402 162.5,182.891 r90 bottom value=1uF
C111 "GCM188R71H154KA64D" FP-GCM188-0_1-IPC_C 157.377,182.25 r0 top
C112 "GRM1885C1H103JA01D" 0603 188,197.8 r90 bottom value=0.01uF
C113 "GRM1885C1H103JA01D" 0603 207,194.8 r90 bottom value=0.01uF
C114 "GRM155R71H331KA01D" 0402 167,179.8 r270 bottom value=330pF
C116 "C0402C104K4RACAUTO" 0402 234,165 r180 top value=0.1uF
D1 "STBY" LTST-C170KFKT_Orange 238.75,124 r0 top value=Orange
D2 "FAULT" LED_LTST-C170_Red 238.75,127.5 r0 top value=Red
D3 "PD" LTST-C170KFKT_Orange 238.75,120.5 r0 top value=Orange
D4 "SMBJ33CA-13-F" SMB-Bi 135.822,129.639 r90 top value=33V
D5 "LTST-C170KGKT" LTST-C170KGKT_Green 111,102.55 r90 top value="IOVDD POWER"
D6 "LTST-C170KGKT" LTST-C170KGKT_Green 115,102.55 r90 top value="PVDD POWER"
D8 "STBY" LTST-C170KFKT_Orange 238.75,174.25 r0 top value=Orange
D9 "FAULT" LED_LTST-C170_Red 238.75,177.75 r0 top value=Red
D10 "PD" LTST-C170KFKT_Orange 238.75,170.75 r0 top value=Orange
D11 "LTST-C170KGKT" LTST-C170KGKT_Green 119.01,102.54 r90 top value=PORZ
FID1 "Fiducial" Fiducial10-20 106,188 r270 top
FID2 "Fiducial" Fiducial10-20 243,191 r270 top
FID3 "Fiducial" Fiducial10-20 242,109 r270 top
FID4 "Fiducial" Fiducial10-20 106,188 r180 bottom
FID5 "Fiducial" Fiducial10-20 243,191 r180 bottom
FID6 "Fiducial" Fiducial10-20 242,109 r180 bottom
H1 "ATS-TI1OP-1918-C1-R0" FP-ATS-TI1OP-1918-C1-R0_HTSNK_41MM4_20MM0-MFG 168,175 r90 top locked
H2 "ATS-TI1OP-1918-C1-R0" FP-ATS-TI1OP-1918-C1-R0_HTSNK_41MM4_20MM0-MFG 168,125 r90 top locked
J1 "QTE-040-01-L-D-A" FP-QTE-040-01-L-D-A_HDR80-MFG 107.62,150.8 r270 bottom locked
J2 "TSW-116-07-G-D" TSW-116-07-G-D 118.11,176.53 r270 top
J3 "TSW-108-07-G-D" TSW-108-07-G-D 118.11,144.78 r270 top
J4 "7006" Keystone_7006 194.31,116.84 r0 top locked
J5 "7007" Keystone_7007 213.36,116.84 r0 top locked
J6 "7006" Keystone_7006 203.835,133.35 r0 top locked
J7 "7007" Keystone_7007 222.885,133.35 r0 top locked
J8 "7006" Keystone_7006 203.835,106.045 r0 top locked
J9 "7007" Keystone_7007 222.885,106.045 r0 top locked
J10 "7006" Keystone_7006 194.31,144.145 r0 top locked
J11 "7007" Keystone_7007 213.36,144.145 r0 top locked
J12 "22-23-2031" Molex_22-23-2031 134.12,196.5 r180 top
J13 "7006" Keystone_7006 147.32,106.68 r0 top
J15 "7007" Keystone_7007 128.27,106.68 r0 top
J17 "7006" Keystone_7006 194.31,167.005 r0 top locked
J18 "7007" Keystone_7007 213.36,167.005 r0 top locked
J19 "7006" Keystone_7006 203.835,183.515 r0 top locked
J20 "7007" Keystone_7007 222.885,183.515 r0 top locked
J21 "7006" Keystone_7006 203.835,156.21 r0 top locked
J22 "7007" Keystone_7007 222.885,156.21 r0 top locked
J23 "7006" Keystone_7006 194.31,194.31 r0 top locked
J24 "7007" Keystone_7007 213.36,194.31 r0 top locked
J25 "22-23-2031" Molex_22-23-2031 143.12,196.5 r180 top
L1 "VCMT053T-3R3MN5" VCMT053T 181.7,122 r0 top value=3.3uH
L2 "VCMT053T-3R3MN5" VCMT053T 181.7,128 r0 top value=3.3uH
L3 "VCMT053T-3R3MN5" VCMT053T 154.25,122 r180 top value=3.3uH
L4 "VCMT053T-3R3MN5" VCMT053T 154.25,128 r180 top value=3.3uH
L6 "VCMT053T-3R3MN5" VCMT053T 181.7,172 r0 top value=3.3uH
L7 "VCMT053T-3R3MN5" VCMT053T 181.7,178 r0 top value=3.3uH
L8 "VCMT053T-3R3MN5" VCMT053T 154.3,172 r180 top value=3.3uH
L9 "VCMT053T-3R3MN5" VCMT053T 154.3,178 r180 top value=3.3uH
Logo1 "CE Mark" CE_Mark_5mm 237,193 r180 bottom
Logo2 "Texas Instruments" TI_Symbol_Overlay_Small 235,146 r0 top
Logo3 "FCC disclaimer" FCC_disclaimer 100.5,151.3 r270 bottom
Logo4 "WEEE logo" WEEE_Minimum 229,193 r180 bottom
Q1 "BSS223PWH6327" SOT-323 235.5,124 r0 top value=-20V
Q2 "BSS223PWH6327" SOT-323 235.5,127.5 r0 top value=-20V
Q3 "BSS223PWH6327" SOT-323 235.5,120.5 r0 top value=-20V
Q4 "SI7892BDP" PowerPAK_SO-8 134.444,137.287 r270 top value=30V
Q5 "SI7892BDP" PowerPAK_SO-8 135.5,144.929 r90 top value=30V
Q6 "BSS123W-7-F" SOT-323 111,110.55 r270 top value=100V
Q7 "BSS123W-7-F" SOT-323 115,110.55 r270 top value=100V
Q9 "BSS223PWH6327" SOT-323 235.5,174.25 r0 top value=-20V
Q10 "BSS223PWH6327" SOT-323 235.5,177.75 r0 top value=-20V
Q11 "BSS223PWH6327" SOT-323 235.5,170.75 r0 top value=-20V
Q12 "BSS123W-7-F" SOT-323 119,110.55 r270 top value=100V
R1 "ERJ-2GEJ220X" 0402 129.06,183.994 r270 top value=22
R2 "RC0603FR-0710KL" 0603 138.576,157.177 r0 top value=10.0k
R3 "ERJ-2GEJ220X" 0402 139.225,186.618 r0 top value=22
R4 "ERJ-3GEY0R00V" FP-ERJ-3GEY0R00V_0603-IPC_B 138.527,155.177 r180 top
R5 "ERJ-2GEJ361X" 0402 117.253,102.1 r90 top value=360
R6 "RC0603FR-07100KL" 0603 129.033,187.422 r270 top value=100k
R7 "RC0603FR-074K99L" 0603 134.874,166.878 r0 top value=4.99k
R8 "RC0603FR-074K99L" 0603 128.27,165.824 r270 top value=4.99k
R9 "ERJ-2GEJ220X" 0402 129,178.2 r180 top value=22
R10 "ERJ-2GEJ220X" 0402 139.1,179.75 r0 top value=22
R11 "ERJ-2GEJ220X" 0402 139.1,177.25 r0 top value=22
R12 "ERJ-2GEJ220X" 0402 139.1,178.5 r0 top value=22
R13 "RC0603FR-07100KL" 0603 131.95,181.17 r180 top value=100k
R14 "ERJ-2GEJ220X" 0402 129.7,170.4 r270 top value=22
R15 "ERJ-2GEJ220X" 0402 138.4,171.7 r270 top value=22
R16 "RC0603FR-07100KL" 0603 131.95,174 r180 top value=100k
R17 "RC0603FR-0710KL" 0603 130.041,161.879 r90 top value=10.0k
R18 "RC0603FR-0710KL" 0603 139.35,162.5 r180 top value=10.0k
R19 "ERJ-2GEJ220X" 0402 131.35,166.6 r0 top value=22
R20 "RC0603FR-0710KL" 0603 139.35,164.1 r180 top value=10.0k
R21 "RC0603FR-07100KL" 0603 128.3,161.9 r90 top value=100k
R22 "RMCF0402FT100K" 0402 139.225,187.845 r0 top value=100k
R23 "RMCF0402FT100K" 0402 139.1,181 r0 top value=100k
R24 "RMCF0402FT100K" 0402 139.7,171.7 r270 top value=100k
R25 "RMCF0402FT100K" 0402 175.25,132.25 r0 top value=100k
R26 "CRCW06033R30JNEA" 0603 168.8,123.2 r90 bottom value=3.3
R27 "ERJ-2GEJ511X" 0402 119.01,112.559 r0 top value=510
R28 "ERJ-3GEYJ102V" FP-ERJ-3GEYJ102V_0603-MFG 147,133.275 r270 top
R29 "ERJ-3GEYJ102V" FP-ERJ-3GEYJ102V_0603-MFG 145,133.275 r90 top
R30 "ERJ-3GEYJ102V" FP-ERJ-3GEYJ102V_0603-MFG 166.49,117.6 r90 bottom
R31 "CRCW06033R30JNEA" 0603 168.8,126.7 r270 bottom value=3.3
R32 "RC0603FR-07110KL" 0603 231.5,115.7 r90 top value=110k
R33 "ERJ-2GEJ220X" 0402 175.25,131 r180 top value=22
R34 "CRCW06033R30JNEA" 0603 167,123.2 r90 bottom value=3.3
R35 "RC0603FR-07110KL" 0603 231.5,166 r90 top value=110k
R36 "CRCW06033R30JNEA" 0603 167,126.7 r270 bottom value=3.3
R37 "ERJ-2RKF2200X" 0402 230.75,124 r270 top value=220
R38 "RC0603FR-07100KL" 0603 131.586,153.127 r0 top value=100k
R39 "ERJ-2RKF2200X" 0402 229.5,124 r90 top value=220
R40 "ERJ-2RKF2200X" 0402 230.75,120.5 r270 top value=220
R41 "ERJ-3GEY0R00V" FP-ERJ-3GEY0R00V_0603-IPC_B 108.049,145.9 r180 top
R42 "ERJ-2RKF2200X" 0402 230.75,127.5 r270 top value=220
R43 "ERJ-2GEJ511X" 0402 232.75,124.75 r180 top value=510
R44 "ERJ-2GEJ511X" 0402 232.75,128.25 r180 top value=510
R45 "ERJ-2RKF2200X" 0402 229.5,120.5 r90 top value=220
R46 "ERJ-2RKF2200X" 0402 229.5,127.5 r90 top value=220
R47 "RMCF0402FT10K0" 0402 245.606,116.006 r270 top value=10.0k
R48 "ERJ-2GEJ511X" 0402 232.75,121.25 r180 top value=510
R49 "ERJ-3GEY0R00V" FP-ERJ-3GEY0R00V_0603-IPC_B 130.316,139.692 r270 top
R50 "RC0603FR-07100KL" 0603 132,132.512 r180 top value=100k
R51 "RC0603FR-076K8L" 0603 132.004,130.988 r0 top value=6.80k
R52 "RC0603FR-0710KL" 0603 129.032,157.988 r90 top value=10.0k
R53 "ERJ-3GEY0R00V" FP-ERJ-3GEY0R00V_0603-IPC_B 128.204,155.177 r0 top
R54 "RC0603FR-0710KL" 0603 135.179,157.177 r0 top value=10.0k
R55 "ERJ-3GEY0R00V" FP-ERJ-3GEY0R00V_0603-IPC_B 128.23,139.692 r90 top
R56 "ERJ-2GEJ361X" 0402 109.167,102.1 r90 top value=360
R57 "ERJ-2GEJ361X" 0402 113.278,102.1 r90 top value=360
R58 "ERJ-2RKF2200X" 0402 230.75,174.25 r270 top value=220
R59 "ERJ-2RKF1002X" 0402 115.1,113.85 r180 top value=10.0k
R60 "ERJ-2RKF2200X" 0402 229.5,174.25 r90 top value=220
R61 "ERJ-2GEJ511X" 0402 111,112.6 r0 top value=510
R62 "ERJ-2GEJ511X" 0402 115.1,112.6 r0 top value=510
R63 "ERJ-2RKF2200X" 0402 230.75,170.75 r270 top value=220
R64 "ERJ-2RKF1002X" 0402 109,112 r270 top value=10.0k
R65 "ERJ-2RKF1002X" 0402 113,112 r270 top value=10.0k
R66 "ERJ-2RKF2200X" 0402 230.75,177.75 r270 top value=220
R67 "RMCF0402FT100K" 0402 131.486,183.148 r180 top value=100k
R68 "RMCF0402FT100K" 0402 129,176.9 r180 top value=100k
R69 "RMCF0402FT100K" 0402 128.365,170.4 r270 top value=100k
R70 "RMCF0402FT100K" 0402 175.35,182.303 r0 top value=100k
R71 "CRCW06033R30JNEA" 0603 169,173.2 r90 bottom value=3.3
R72 "ERJ-2RKF2200X" 0402 229.5,170.75 r90 top value=220
R73 "ERJ-3GEYJ102V" FP-ERJ-3GEYJ102V_0603-MFG 149,181.975 r270 top
R74 "ERJ-3GEY0R00V" FP-ERJ-3GEY0R00V_0603-MFG 147,181.975 r90 top
R75 "ERJ-3GEYJ102V" FP-ERJ-3GEYJ102V_0603-MFG 166.382,167.607 r90 bottom
R76 "CRCW06033R30JNEA" 0603 169,176.8 r270 bottom value=3.3
R77 "ERJ-2RKF2200X" 0402 229.5,177.75 r90 top value=220
R78 "ERJ-2GEJ220X" 0402 175.35,181 r180 top value=22
R79 "CRCW06033R30JNEA" 0603 167,173.2 r90 bottom value=3.3
R81 "CRCW06033R30JNEA" 0603 167,176.8 r270 bottom value=3.3
R83 "ERJ-3GEY0R00V" FP-ERJ-3GEY0R00V_0603-IPC_B 135.067,155.177 r0 top
R86 "ERJ-3GEY0R00V" FP-ERJ-3GEY0R00V_0603-IPC_B 108.1,149.8 r180 top
R88 "ERJ-2GEJ511X" 0402 232.75,175 r180 top value=510
R89 "ERJ-2GEJ511X" 0402 232.75,178.5 r180 top value=510
R90 "RMCF0402FT10K0" 0402 245.5,166.4 r270 top value=10.0k
R93 "ERJ-2GEJ511X" 0402 232.75,171.5 r180 top value=510
R94 "RC0603FR-0710KL" 0603 131.678,157.177 r0 top value=10.0k
R95 "ERJ-3GEY0R00V" FP-ERJ-3GEY0R00V_0603-IPC_B 131.629,155.177 r0 top
R96 "RC0603FR-07357KL" 0603 127.5,150.7 r90 top value=357k
S1 "CAS-120TA" SW_CAS-120TA 124,145.25 r0 top
SW2 "CFS-0103TB" FP-CFS-0103TB_SMT_SW_6MM40_3MM95-MFG 238.914,116.5 r180 top
SW4 "CFS-0103TB" FP-CFS-0103TB_SMT_SW_6MM40_3MM95-MFG 238.914,167 r180 top
TP1 "AVDD" TP_SM_1MM 172.361,132.938 r180 bottom
TP2 "AVDD" TP_SM_1MM 170,132.303 r180 bottom
TP3 "AVDD" TP_SM_1MM 172.361,131.668 r180 bottom
TP4 "5000" Keystone5000 118,121 r90 top
TP5 "5003" Keystone5003 126,125 r90 top
TP6 "5000" Keystone5000 126,121 r90 top
TP7 "AVDD" TP_SM_1MM 161.929,115.2 r180 bottom
TP8 "AVDD" TP_SM_1MM 165.725,119.732 r180 bottom
TP9 "CPC_TOP" TP_SM_1MM 180.3,113.132 r0 top
TP10 "CPC_BOT" TP_SM_1MM 180.3,111.5 r90 top
TP11 "CP" TP_SM_1MM 172.361,118.837 r90 bottom
TP12 "VR_DIG" TP_SM_1MM 163.25,130.836 r90 bottom
TP13 "FAULT" TP_SM_1MM 233.5,126 r90 top
TP14 "FAULT" TP_SM_1MM 233.5,129.5 r90 top
TP15 "VR_DIG" TP_SM_1MM 130,192 r90 top
TP16 "FAULT" TP_SM_1MM 233.5,122.5 r90 top
TP17 "AVDD" TP_SM_1MM 171.25,183.25 r270 bottom
TP18 "AVDD" TP_SM_1MM 168.25,183.25 r270 bottom
TP19 "AVDD" TP_SM_1MM 170.5,182 r270 bottom
TP20 "5003" Keystone5003 122,125 r90 top
TP22 "5003" Keystone5003 118,125 r90 top
TP23 "AVDD" TP_SM_1MM 161.81,165.192 r90 bottom
TP24 "AVDD" TP_SM_1MM 156.6,165.7 r90 top
TP25 "CPC_TOP" TP_SM_1MM 169,168.2 r90 bottom
TP26 "CPC_BOT" TP_SM_1MM 180.3,163 r90 top
TP27 "CP" TP_SM_1MM 180.3,164.6 r90 top
TP28 "VR_DIG" TP_SM_1MM 161.25,183.658 r90 bottom
TP29 "FAULT" TP_SM_1MM 233.5,176.25 r90 top
TP30 "FAULT" TP_SM_1MM 233.5,179.75 r90 top
TP31 "VR_DIG" TP_SM_1MM 139,191.75 r90 top
TP32 "FAULT" TP_SM_1MM 233.5,172.75 r90 top
TP33 "5000" Keystone5000 122,121 r90 top
TP34 "5001" Keystone5001 114,125 r90 top
TP35 "5001" Keystone5001 114,121 r90 top
U1 "LMK1C1102PWR" PW0008A-MFG 134.073,185.648 r0 top
U2 "LMK1C1104PWR" PW0008A-MFG 134.067,178.565 r0 top
U3 "LMK1C1102PWR" PW0008A-MFG 134.05,171.375 r0 top
U4 "CAT24C04WI-GT3" FP-CAT24C04WI-GT3_SOIC8-IPC_C 134.302,163.314 r180 top
U5 "TAS6754QDKQRQ1" DKQ0056C-MFG 168,125 r180 top locked
U6 "PartNumber" DDF0008A-MFG 129,135.418 r0 top
U7 "TAS6754QDKQRQ1" DKQ0056C-MFG 168,175 r180 top locked
U8 "SN74AUP1G17DRLR" DRL0005A 131.886,150.805 r90 top
ZZ2 "These assemblies are ESD sensitive, ESD precautions shall be observed." AssemblyNote 0,457.5 r0 top
ZZ3 "These assemblies must be clean and free from flux and all contaminants. Use of no clean flux is not acceptable." AssemblyNote 0,455 r0 top
ZZ4 "These assemblies must comply with workmanship standards IPC-A-610 Class 2, unless otherwise specified." AssemblyNote 0,452.5 r0 top

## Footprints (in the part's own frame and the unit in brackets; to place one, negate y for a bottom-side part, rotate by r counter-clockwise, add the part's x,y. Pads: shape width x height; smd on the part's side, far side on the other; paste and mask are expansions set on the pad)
0402 [mm] "0402 from SM-752 data"
  rect 0.8x0.6 smd: 1(-0.6,0) 2(0.6,0)
  silkscreen extent -1.22,-0.52 1.22,0.52, body extent -0.55,-0.3 0.55,0.3, height 0.6
0603 [mm] "0603 from SM-752 data"
  rect 1x0.95 smd: 1(-0.8,0) 2(0.8,0)
  silkscreen extent -1.52,-0.69 1.52,0.69, body extent -0.87,-0.47 0.87,0.47, height 1
0805_HV [mil] "0805 with 30mil clearance between pads"
  rect 50x63 smd: 1(-40,0) 2(40,0)
  silkscreen extent -74,-40 74,40, body extent -43,-29 43,29, height 57
1210_280 [mm] "SMD, 2-Leads, Body 3.6x2.8mm, Height 2.8mm"
  rect 1.1x2.2 smd: 1(-1.65,0) 2(1.65,0)
  silkscreen extent -0.84,-1.4 0.84,1.4, body extent -1.8,-1.4 1.8,1.4, height 2.8
AssemblyNote [mm] "Assembly Note"
CE_Mark_5mm [mm] "Minimum text height for CE Mark"
  silkscreen extent -3.5,-2.5 3.5,2.5
DDF0008A-MFG [mm]
  rrect22% 1.05x0.45 smd paste+0 mask+0: 1(-1.3,0.975) 2(-1.3,0.325) 3(-1.3,-0.325) 4(-1.3,-0.975) 5(1.3,-0.975) 6(1.3,-0.325) 7(1.3,0.325) 8(1.3,0.975)
  silkscreen extent -2.5,-1.48 0.4,1.48, body extent -1.92,-1.73 1.92,1.73, height 0.25
DKQ0056C-MFG [mm]
  rrect25% 1.9x0.4 smd paste+0 mask+0: 1(-4.75,8.572) 2(-4.75,7.938) 3(-4.75,7.302) 4(-4.75,6.667) 5(-4.75,6.032) 6(-4.75,5.397) 7(-4.75,4.762) 8(-4.75,4.127) 9(-4.75,3.492) 10(-4.75,2.857) 11(-4.75,2.222) 12(-4.75,1.587) 13(-4.75,0.952) 14(-4.75,0.317) 15(-4.75,-0.318) 16(-4.75,-0.953) 17(-4.75,-1.588) 18(-4.75,-2.223) 19(-4.75,-2.858) 20(-4.75,-3.493) 21(-4.75,-4.128) 22(-4.75,-4.763) 23(-4.75,-5.398) 24(-4.75,-6.033) 25(-4.75,-6.667) 26(-4.75,-7.302) 27(-4.75,-7.938) 28(-4.75,-8.572) 29(4.75,-8.572) 30(4.75,-7.938) 31(4.75,-7.302) 32(4.75,-6.667) 33(4.75,-6.032) 34(4.75,-5.397) 35(4.75,-4.762) 36(4.75,-4.127) 37(4.75,-3.492) 38(4.75,-2.857) 39(4.75,-2.222) 40(4.75,-1.587) 41(4.75,-0.952) 42(4.75,-0.317) 43(4.75,0.318) 44(4.75,0.953) 45(4.75,1.588) 46(4.75,2.223) 47(4.75,2.858) 48(4.75,3.493) 49(4.75,4.128) 50(4.75,4.763) 51(4.75,5.398) 52(4.75,6.033) 53(4.75,6.667) 54(4.75,7.302) 55(4.75,7.938) 56(4.75,8.572)
  silkscreen extent -6.37,-9.27 3.79,9.27, body extent -5.8,-9.52 5.8,9.52, height 0.25
DRL0005A [mm] "SOTFL, 5-Flat Leads, Body 1.2x1.6x0.6mm, Pitch 0.5mm, TI recommended"
  rrect33% 0.67x0.3 smd: 1(-0.74,0.5) 2(-0.74,0) 3(-0.74,-0.5) 4(0.74,-0.5) 5(0.74,0.5)
  silkscreen extent -0.9,-0.95 0.5,0.95, body extent -0.85,-0.85 0.85,0.85, height 0.62
FCC_disclaimer [mm]
Fiducial10-20 [mm]
  round 1 smd mask+0.5: 1(0,0)
  L1 keep-out circle w1.178: c0,0 r0.5
FP-ATS-TI1OP-1918-C1-R0_HTSNK_41MM4_20MM0-MFG [mm]
  round 4.75 hole 3.15 paste-2539.97 mask+0: 1(-16.25,0) 2(16.25,0)
  silkscreen extent -20.89,-10.19 20.89,10.19, body extent -20.99,-10.29 20.99,10.29, height 0.25
FP-CAT24C04WI-GT3_SOIC8-IPC_C [mm]
  rrect18% 1.874x0.545 smd paste+0 mask+0: 1(-2.316,1.905)
  rrect100% 1.874x0.545 smd paste+0 mask+0: 2(-2.316,0.635) 3(-2.316,-0.635) 4(-2.316,-1.905) 5(2.316,-1.905) 6(2.316,-0.635) 7(2.316,0.635) 8(2.316,1.905)
  silkscreen extent -3.93,-2.45 0.88,2.45, body extent -3.35,-2.55 3.35,2.55, height 0.25
FP-CFS-0103TB_SMT_SW_6MM40_3MM95-MFG [mm]
  rrect6% 2.5x1.8 smd paste+0 mask+0: 1(-4.55,0) 2(4.55,0)
  silkscreen extent -3.35,-2.12 3.35,2.12, body extent -5.9,-2.22 5.9,2.22, height 0.25
FP-ERJ-3GEY0R00V_0603-IPC_B [mm]
  rrect10% 0.957x0.962 smd paste+0 mask+0: 1(-0.751,0) 2(0.751,0)
  silkscreen extent -1.23,-0.88 1.23,0.88, body extent -1.48,-0.73 1.48,0.73, height 0.25
FP-ERJ-3GEY0R00V_0603-MFG [mm]
  rrect15% 0.65x0.9 smd paste+0 mask+0: 1(-0.725,0) 2(0.725,0)
  silkscreen extent -1.03,-0.87 1.03,0.87, body extent -1.15,-0.58 1.15,0.58, height 0.25
FP-ERJ-3GEYJ102V_0603-MFG [mm]
  rrect15% 0.65x0.9 smd paste+0 mask+0: 1(-0.725,0) 2(0.725,0)
  silkscreen extent -1.03,-0.87 1.03,0.87, body extent -1.15,-0.58 1.15,0.58, height 0.25
FP-GCJ21B-0_3-IPC_A [mm]
  rect 1.553x1.556 smd paste+0 mask+0: 1(-0.925,0) 2(0.925,0)
  silkscreen extent -1.7,-1.18 1.7,1.18, body extent -1,-0.63 1,0.63, height 1.45
FP-GCJ188-0_2-IPC_C [mm]
  rect 0.855x0.812 smd paste+0 mask+0: 1(-0.625,0) 2(0.625,0)
  silkscreen extent -1.05,-0.85 1.05,0.85, body extent -1.15,-0.55 1.15,0.55, height 0.25
FP-GCM188-0_1-IPC_C [mm]
  rect 0.759x0.812 smd paste+0 mask+0: 1(-0.627,0) 2(0.627,0)
  silkscreen extent -1.01,-0.85 1.01,0.85, body extent -0.8,-0.4 0.8,0.4, height 0.9
FP-QTE-040-01-L-D-A_HDR80-MFG [mm]
  rrect22% 0.46x1.45 smd paste+0 mask+0: 1(-17.6,3.085) 2(-17.6,-3.085) 3(-16.8,3.085) 4(-16.8,-3.085) 5(-16,3.085) 6(-16,-3.085) 7(-15.2,3.085) 8(-15.2,-3.085) 9(-14.4,3.085) 10(-14.4,-3.085) 11(-13.6,3.085) 12(-13.6,-3.085) 13(-12.8,3.085) 14(-12.8,-3.085) 15(-12,3.085) 16(-12,-3.085) 17(-11.2,3.085) 18(-11.2,-3.085) 19(-10.4,3.085) 20(-10.4,-3.085) 21(-9.6,3.085) 22(-9.6,-3.085) 23(-8.8,3.085) 24(-8.8,-3.085) 25(-8,3.085) 26(-8,-3.085) 27(-7.2,3.085) 28(-7.2,-3.085) 29(-6.4,3.085) 30(-6.4,-3.085) 31(-5.6,3.085) 32(-5.6,-3.085) 33(-4.8,3.085) 34(-4.8,-3.085) 35(-4,3.085) 36(-4,-3.085) 37(-3.2,3.085) 38(-3.2,-3.085) 39(-2.4,3.085) 40(-2.4,-3.085) 41(2.4,3.085) 42(2.4,-3.085) 43(3.2,3.085) 44(3.2,-3.085) 45(4,3.085) 46(4,-3.085) 47(4.8,3.085) 48(4.8,-3.085) 49(5.6,3.085) 50(5.6,-3.085) 51(6.4,3.085) 52(6.4,-3.085) 53(7.2,3.085) 54(7.2,-3.085) 55(8,3.085) 56(8,-3.085) 57(8.8,3.085) 58(8.8,-3.085) 59(9.6,3.085) 60(9.6,-3.085) 61(10.4,3.085) 62(10.4,-3.085) 63(11.2,3.085) 64(11.2,-3.085) 65(12,3.085) 66(12,-3.085) 67(12.8,3.085) 68(12.8,-3.085) 69(13.6,3.085) 70(13.6,-3.085) 71(14.4,3.085) 72(14.4,-3.085) 73(15.2,3.085) 74(15.2,-3.085) 75(16,3.085) 76(16,-3.085) 77(16.8,3.085) 78(16.8,-3.085) 79(17.6,3.085) 80(17.6,-3.085)
  rrect16% 2.54x0.64 smd paste+0 mask+0: P1(-18.45,0) P1(-1.56,0) P2(1.55,0) P2(18.44,0)
  rrect16% 4.7x0.64 smd paste+0 mask+0: P1(-13.18,0) P1(-6.83,0) P2(6.82,0) P2(13.17,0)
  round 1.02 hole 1.02 unplated paste-2539.97 mask+0: ""(-19.24,2.035) ""(19.24,2.035)
  silkscreen extent -20.07,-3.01 20.07,3.74, body extent -20,-3.56 20,3.56, height 4.35
Keystone5000 [mil] "For Keystone 500x miniature loop terminals"
  round 80 hole 40: 1(0,0)
  silkscreen extent -52,-52 52,52, body extent -49,-49 49,49, height 182
Keystone5001 [mil] "For Keystone 500x miniature loop terminals"
  round 80 hole 40: 1(0,0)
  silkscreen extent -52,-52 52,52, body extent -49,-49 49,49, height 182
Keystone5003 [mil] "For Keystone 500x miniature loop terminals"
  round 80 hole 40: 1(0,0)
  silkscreen extent -52,-52 52,52, body extent -49,-49 49,49, height 182
Keystone_7006 [mm] "KEYSTONE"
  round 8.5 hole 3.658: 1(0,0)
  silkscreen extent -4.8,-4.8 4.8,4.8, body extent -5.68,-5.69 5.7,5.69, height 26.47
Keystone_7007 [mm] "KEYSTONE"
  round 8.5 hole 3.658: 1(0,0)
  silkscreen extent -4.8,-4.8 4.8,4.8, body extent -5.71,-5.66 5.67,5.72, height 26.48
LED_LTST-C170_Red [mm] "LITE-ON"
  rect 1.2x1.2 smd: 1(-1.05,0) 2(1.05,0)
  silkscreen extent -1.6,-1 2.2,1, body extent -1.05,-0.67 1.05,0.67, height 1.1
LTST-C170KFKT_Orange [mm] "LITE-ON"
  rect 1.2x1.2 smd: 1(-1.05,0) 2(1.05,0)
  silkscreen extent -1.6,-1 2.2,1, body extent -1.05,-0.67 1.05,0.67, height 1.1
LTST-C170KGKT_Green [mm] "LITE-ON"
  rect 1.2x1.2 smd: 1(-1.05,0) 2(1.05,0)
  silkscreen extent -1.6,-1 2.2,1, body extent -1.05,-0.67 1.05,0.67, height 1.1
Molex_22-23-2031 [mm] "Header, 2.54mm, 3x1, TH"
  rect 1.55x1.55 hole 1.02: 1(-2.54,0)
  round 1.55 hole 1.02: 2(0,0) 3(2.54,0)
  silkscreen extent -4.1,-3.18 3.73,3.18, body extent -3.73,-3.25 3.73,3.1, height 10.67
PowerPAK_SO-8 [mil] "Vishay PowerPAK SO-8, Body 5.3x6.0mm (max), Pitch 1.27mm, IPC Medium Density"
  rect 50x24 smd mask+2.99: 1(-109.5,75) 2(-109.5,25) 3(-109.5,-25) 4(-109.5,-75)
  rect 48x24 smd mask+2.99: 5(109.5,-75) 8(109.5,75)
  rect 48x24 smd paste-12 mask+2.99: 6(109.5,-25) 7(109.5,25)
  rect 150x154 smd paste-75 mask+2.99: 9(22.5,0)
  silkscreen extent -130,-104 59,104, body extent -121,-102 121,102, height 43
PW0008A-MFG [mm]
  rrect22% 1.5x0.45 smd paste+0 mask+0: 1(-2.9,0.975) 2(-2.9,0.325) 3(-2.9,-0.325) 4(-2.9,-0.975) 5(2.9,-0.975) 6(2.9,-0.325) 7(2.9,0.325) 8(2.9,0.975)
  silkscreen extent -2.99,-1.55 1.77,1.84, body extent -3.75,-1.8 3.75,1.8, height 0.25
SM_RADIAL_10BMM [mm] "Nichicon 10x10"
  rect 4x2.5 smd: 1(-4,0) 2(4,0)
  silkscreen extent -5.25,-5.25 5.25,5.25, body extent -5.25,-5.25 5.25,5.25, height 10.5
SMB-Bi [mm] "Molded Diode, 2-Leads, Body 5.4x3.6mm, IPC Medium Density, based on OnSemi component dimensions"
  rect 2.159x2.743 smd: 1(-2.21,0) 2(2.21,0)
  silkscreen extent -3.17,-1.99 3.17,1.99, body extent -2.65,-1.85 2.65,1.85, height 2.26
SOT-323 [mm] "Diodes Inc recommended land pattern.  2016-02-24"
  rrect21% 0.6x0.47 smd: 1(-0.95,0.65) 2(-0.95,-0.65) 3(0.95,0)
  silkscreen extent -1.14,-1.22 0.77,1.22, body extent -1.13,-1.13 1.12,1.12, height 1.13
SW_CAS-120TA [mm] "COPAL ELECTRONICS"
  rect 1.6x1 smd: 1(-1.15,1.75) 2(1.15,0) 3(-1.15,-1.75)
  silkscreen extent -2,-2.85 1.4,2.93, body extent -1.4,-2.85 1.4,2.85, height 2.51
TI_Symbol_Overlay_Small [mm]
  silkscreen extent -2.3,-2.23 2.3,2.24
TP_SM_1MM [mm] "1mm Test Point, SMT"
  round 1 smd paste-0.5: 1(0,0)
TSW-108-07-G-D [mm] "Samtec 100mil, 2x8, 230 mil above insulator"
  rrect6% 1.65x1.65 hole 1.016: 1(-8.89,-1.27)
  round 1.65 hole 1.016: 2(-8.89,1.27) 3(-6.35,-1.27) 4(-6.35,1.27) 5(-3.81,-1.27) 6(-3.81,1.27) 7(-1.27,-1.27) 8(-1.27,1.27) 9(1.27,-1.27) 10(1.27,1.27) 11(3.81,-1.27) 12(3.81,1.27) 13(6.35,-1.27) 14(6.35,1.27) 15(8.89,-1.27) 16(8.89,1.27)
  silkscreen extent -10.84,-3.23 10.16,2.54, body extent -10.16,-2.54 10.16,2.54, height 8.38
TSW-116-07-G-D [mm] "Samtec 100mil, 2x16, 230 mil above insulator"
  rrect6% 1.65x1.65 hole 1.016: 1(-19.05,-1.27)
  round 1.65 hole 1.016: 2(-19.05,1.27) 3(-16.51,-1.27) 4(-16.51,1.27) 5(-13.97,-1.27) 6(-13.97,1.27) 7(-11.43,-1.27) 8(-11.43,1.27) 9(-8.89,-1.27) 10(-8.89,1.27) 11(-6.35,-1.27) 12(-6.35,1.27) 13(-3.81,-1.27) 14(-3.81,1.27) 15(-1.27,-1.27) 16(-1.27,1.27) 17(1.27,-1.27) 18(1.27,1.27) 19(3.81,-1.27) 20(3.81,1.27) 21(6.35,-1.27) 22(6.35,1.27) 23(8.89,-1.27) 24(8.89,1.27) 25(11.43,-1.27) 26(11.43,1.27) 27(13.97,-1.27) 28(13.97,1.27) 29(16.51,-1.27) 30(16.51,1.27) 31(19.05,-1.27) 32(19.05,1.27)
  silkscreen extent -21.09,-3.23 20.32,2.54, body extent -20.32,-2.54 20.32,2.54, height 8.38
VCMT053T [mm] "CYNTEC"
  rrect5% 1.9x3.3 smd: 1(-2.05,0) 2(2.05,0)
  silkscreen extent -2.8,-2.85 2.8,2.85, body extent -2.9,-2.72 2.9,2.72, height 3.02
WEEE_Minimum [mm] "WEEElie bin"
  silkscreen extent -2.42,-4.38 2.52,2.65

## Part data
C1 C2: library part CMP-0079604-1, "CAP, CERM, 4.7 µF, 50 V,+/- 10%, X7R, AEC-Q200 Grade 1, 1210", Cap_Case=1210, Manufacturer=Kemet, Supplier Part Number 1=399-7049-1-ND, TempCo=X7R, Tolerance_%=10%, Value2=50V, ValueDisplayed=4.7µF
C3 C4 C5 C6 C57: library part CMP-0006659-2, "CAP, CERM, 0.1 uF, 25 V, +/- 10%, X7R, 0402", Cap_Case=0402, Manufacturer=MuRata, Supplier Part Number 1=490-10698-1-ND, TempCo=X7R, Tolerance_%=10%, Value1=Unknown, Value2=25V, ValueDisplayed=0.1uF
C7 C14 C17 C22 C65 C72 C75 C80: library part CMP-0007136-5, "CAP, CERM, 1 uF, 16 V, +/- 10%, X7R, AEC-Q200 Grade 1, 0603", Cap_Case=0603, Manufacturer=MuRata, Supplier Part Number 1=490-5241-6-ND, TempCo=X7R, Tolerance_%=10%, Value1=Unknown, Value2=16V, ValueDisplayed=1uF
C8 C20 C33 C50 C66 C78 C91 C108: library part CMP-0086249-1, "CAP, CERM, 1 µF, 50 V,+/- 10%, X7R, AEC-Q200 Grade 1, 0805", Cap_Case=0805, Manufacturer=MuRata, TempCo=X7R, Tolerance_%=10%, Value2=50V, ValueDisplayed=1µF
C9 C21 C35 C53 C67 C79 C93 C111: library part CMP-2006-02379-2, "Ceramic Capacitor for Automotive 150nF  ±10% 50VDC X7R 0603 Paper T/R", Capacitance=150nF, Case Code (Imperial)=0603, Case Code (Metric)=1608, Dielectric=X7R, Max Operating Temperature=125°C, Min Operating Temperature=-55°C, Package Quantity=4000, Ratings=AEC-Q200, Tolerance=10%, Voltage Rating=50V
C10 C11 C23 C24 C36 C37 C54 C55 C68 C69 C81 C82 C94 C95 C112 C113: library part CMP-0007174-4, "CAP, CERM, 0.01 uF, 50 V, +/- 5%, C0G/NP0, 0603", Cap_Case=0603, Manufacturer=MuRata, Supplier Part Number 1=490-9666-1-ND, TempCo=C0G/NP0, Tolerance_%=5%, Value1=Unknown, Value2=50V, ValueDisplayed=0.01uF
C12 C51 C52 C70 C109 C110: library part CMP-0064947-2, "CAP, CERM, 1 uF, 6.3 V,+/- 10%, X7R, 0402", Cap_Case=0402, Manufacturer=MuRata, Supplier Part Number 1=490-10024-1-ND, TempCo=X7R, Tolerance_%=10%, Value1=Unknown, Value2=6.3V, ValueDisplayed=1uF
C13 C71: library part CMP-0006623-2, "CAP, CERM, 0.1 uF, 6.3 V, +/- 10%, X7R, 0402", Cap_Case=0402, Manufacturer=MuRata, Supplier Part Number 1=GRM155R70J104KA01D-ND, TempCo=X7R, Tolerance_%=10%, Value1=Unknown, Value2=6.3V, ValueDisplayed=0.1uF
C15 C25 C46 C56 C73 C83 C104 C114: library part CMP-0006687-2, "CAP, CERM, 330 pF, 50 V, +/- 10%, X7R, 0402", Cap_Case=0402, Manufacturer=MuRata, Supplier Part Number 1=490-3247-1-ND, TempCo=X7R, Tolerance_%=10%, Value1=Unknown, Value2=50V, ValueDisplayed=330pF
C16 C18 C74 C76: library part CMP-0007137-5, "CAP, CERM, 1 uF, 16 V, +/- 20%, X7R, AEC-Q200 Grade 1, 0603", Cap_Case=0603, Manufacturer=MuRata, TempCo=X7R, Tolerance_%=20%, Value1=Unknown, Value2=16V, ValueDisplayed=1uF
C19 C77: library part CMP-0007121-4, "CAP, CERM, 2.2 uF, 16 V, +/- 10%, X7R, 0603", Cap_Case=0603, Manufacturer="Taiyo Yuden", Supplier Part Number 1=EMK107BB7225KA-T-ND, TempCo=X7R, Tolerance_%=10%, Value1=Unknown, Value2=16V, ValueDisplayed=2.2uF
C26 C27 C29 C30 C48 C49 C84 C85 C87 C88 C106 C107: library part CMP-06035-059042-1, "Multilayer Ceramic Capacitors MLCC - SMD/SMT 0805 1uF 20%, 50VDC,  X7R 15%", Capacitance=1uF, Case Code (Imperial)=0805, Case Code (Metric)=2012, Max Operating Temperature=125°C, Min Operating Temperature=-55°C, Ratings=AEC-Q200, Tolerance=20%, Voltage Rating=50V
C28: library part CMP-0006658-2, "CAP, CERM, 0.01 uF, 25 V, +/- 10%, X7R, 0402", Cap_Case=0402, Manufacturer=MuRata, Supplier Part Number 1=490-1312-1-ND, TempCo=X7R, Tolerance_%=10%, Value1=Unknown, Value2=25V, ValueDisplayed=0.01uF
C32 C59: library part CMP-0011092-1, "CAP, AL, 390 uF, 35 V, +/- 20%, 0.08 ohm, SMD", Cap_Case=10x10, Manufacturer=Nichicon, Supplier Part Number 1=493-3960-1-ND, Tolerance_%=20%, Value1="0.08 ohm", Value2=35V, ValueDisplayed=390uF
C34 C92: library part CMP-0006351-2, "CAP, CERM, 0.1 uF, 16 V, +/- 10%, X7R, 0402", Cap_Case=0402, Manufacturer=MuRata, Supplier Part Number 1=490-4759-2-ND, TempCo=X7R, Tolerance_%=10%, Value1=Unknown, Value2=16V, ValueDisplayed=0.1uF
C38 C39 C40 C41 C42 C43 C44 C45 C96 C97 C98 C99 C100 C101 C102 C103: library part CMP-2006-02223-2, "Cap Ceramic 0.1uF 50V X7R 10% Pad SMD 0603 Soft Termination +125°C Automotive T/R", Capacitance=100nF, Case Code (Imperial)=0603, Case Code (Metric)=1608, Dielectric=X7R, Max Operating Temperature=125°C, Min Operating Temperature=-55°C, Package Quantity=1, Ratings=AEC-Q200, Tolerance=10%, Voltage Rating=50V
C47 C105: library part CMP-0007393-4, "CAP, CERM, 0.33 uF, 16 V, +/- 10%, X7R, 0603", Cap_Case=0603, Manufacturer=MuRata, Supplier Part Number 1=490-3294-1-ND, TempCo=X7R, Tolerance_%=10%, Value1=Unknown, Value2=16V, ValueDisplayed=0.33uF
C58 C116: library part CMP-0006237-2, "CAP, CERM, 0.1 uF, 16 V, +/- 10%, X7R, AEC-Q200 Grade 1, 0402", Cap_Case=0402, Manufacturer=Kemet, Supplier Part Number 1=399-6828-1-ND, TempCo=X7R, Tolerance_%=10%, Value1=Unknown, Value2=16V, ValueDisplayed=0.1uF
C63: library part CMP-0007144-4, "CAP, CERM, 0.1 uF, 50 V, +/- 10%, X7R, 0603", Cap_Case=0603, Manufacturer=MuRata, Supplier Part Number 1=490-4779-1-ND, TempCo=X7R, Tolerance_%=10%, Value1="0.02 ohm", Value2=50V, ValueDisplayed=0.1uF
C64: library part CMP-0083707-1, "CAP, CERM, 1 µF, 50 V,+/- 20%, X5R, AEC-Q200 Grade 3, 0603", Cap_Case=0603, Manufacturer=TDK, Supplier Part Number 1=445-12510-1-ND, TempCo=X5R, Tolerance_%=20%, Value2=50V, ValueDisplayed=1µF
D1 D3 D8 D10: library part CMP-0002890-1, "LED, Orange, SMD", Color=orange, Manufacturer=Lite-On, PartNumber=LTST-C170KFKT, Supplier Part Number 1=160-1413-1-ND, Value1=W, Value2=2V
D2 D9: library part CMP-0002829-3, "LED, Red, SMD", Color=red, Manufacturer=Lite-On, PartNumber=LTST-C170KRKT, Value1=W, Value2=2V
D4: library part CMP-0005564-3, "Diode, TVS, Bi, 33 V, SMB", Manufacturer="Diodes Inc.", Value1=600W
